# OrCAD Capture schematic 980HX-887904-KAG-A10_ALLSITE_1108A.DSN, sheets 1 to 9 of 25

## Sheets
1 P0043_S4_POWER: size A2
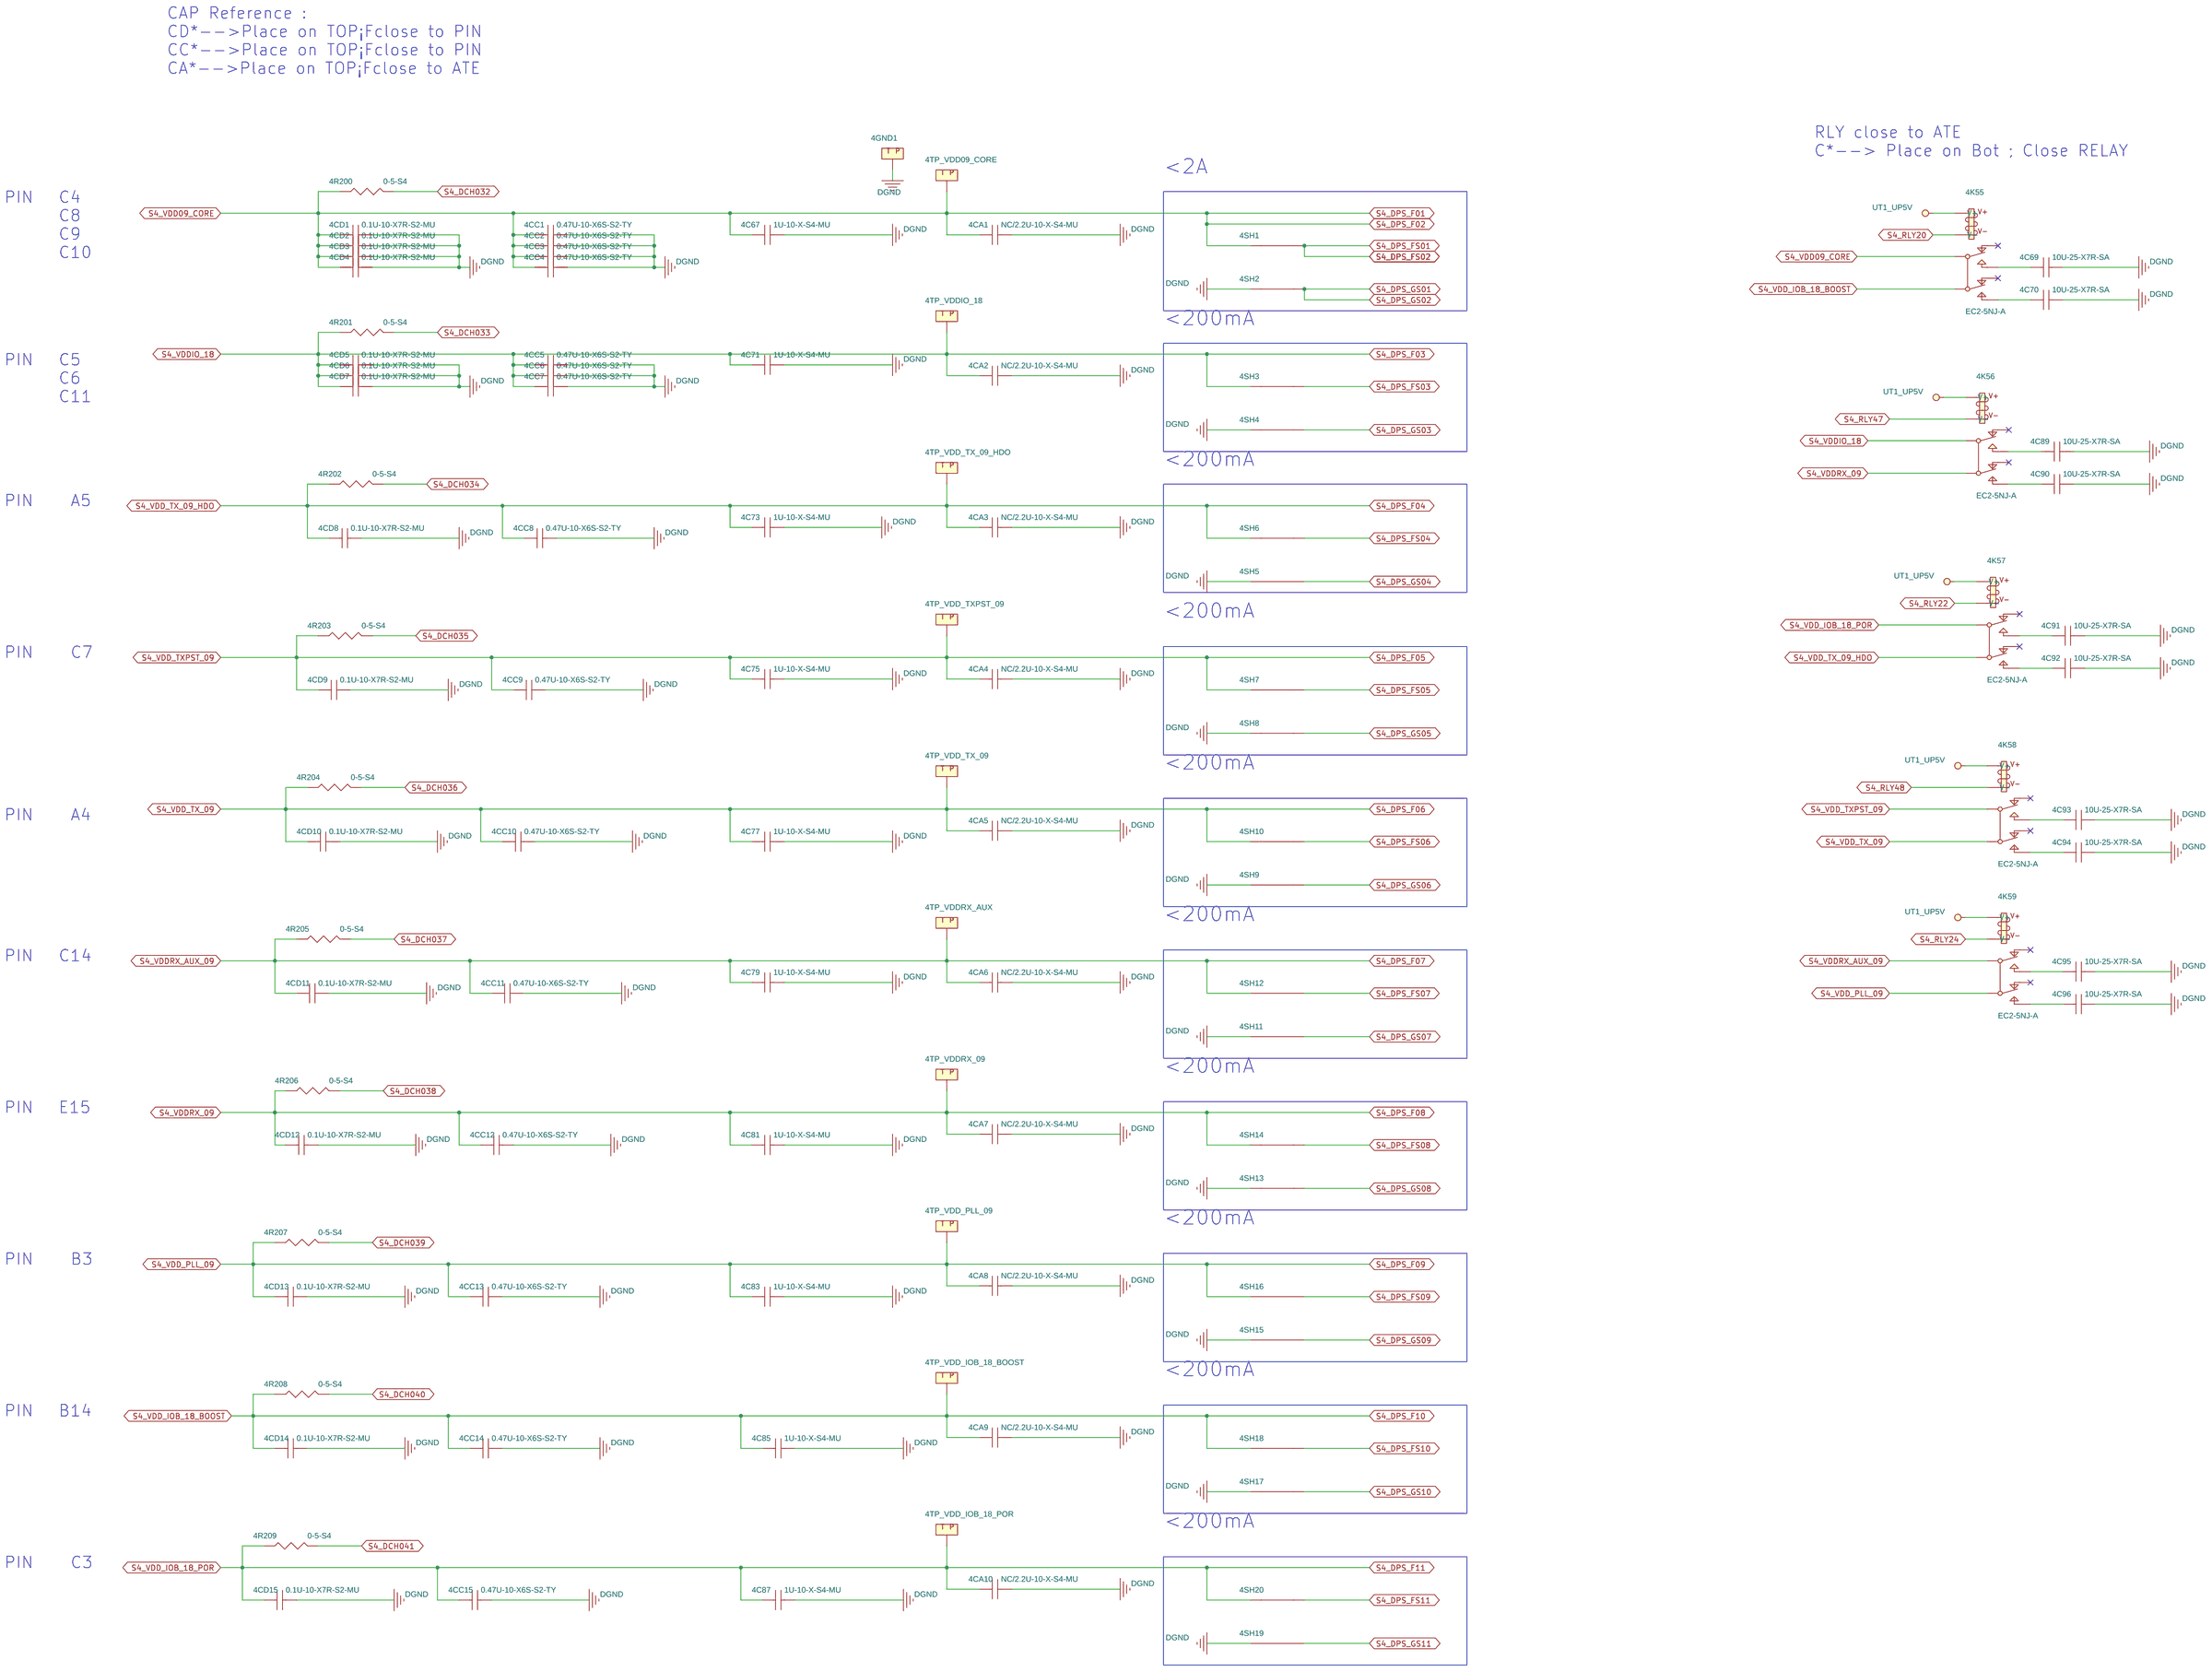
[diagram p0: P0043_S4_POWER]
2 P0042_S4_FLASH_I2C: size A4
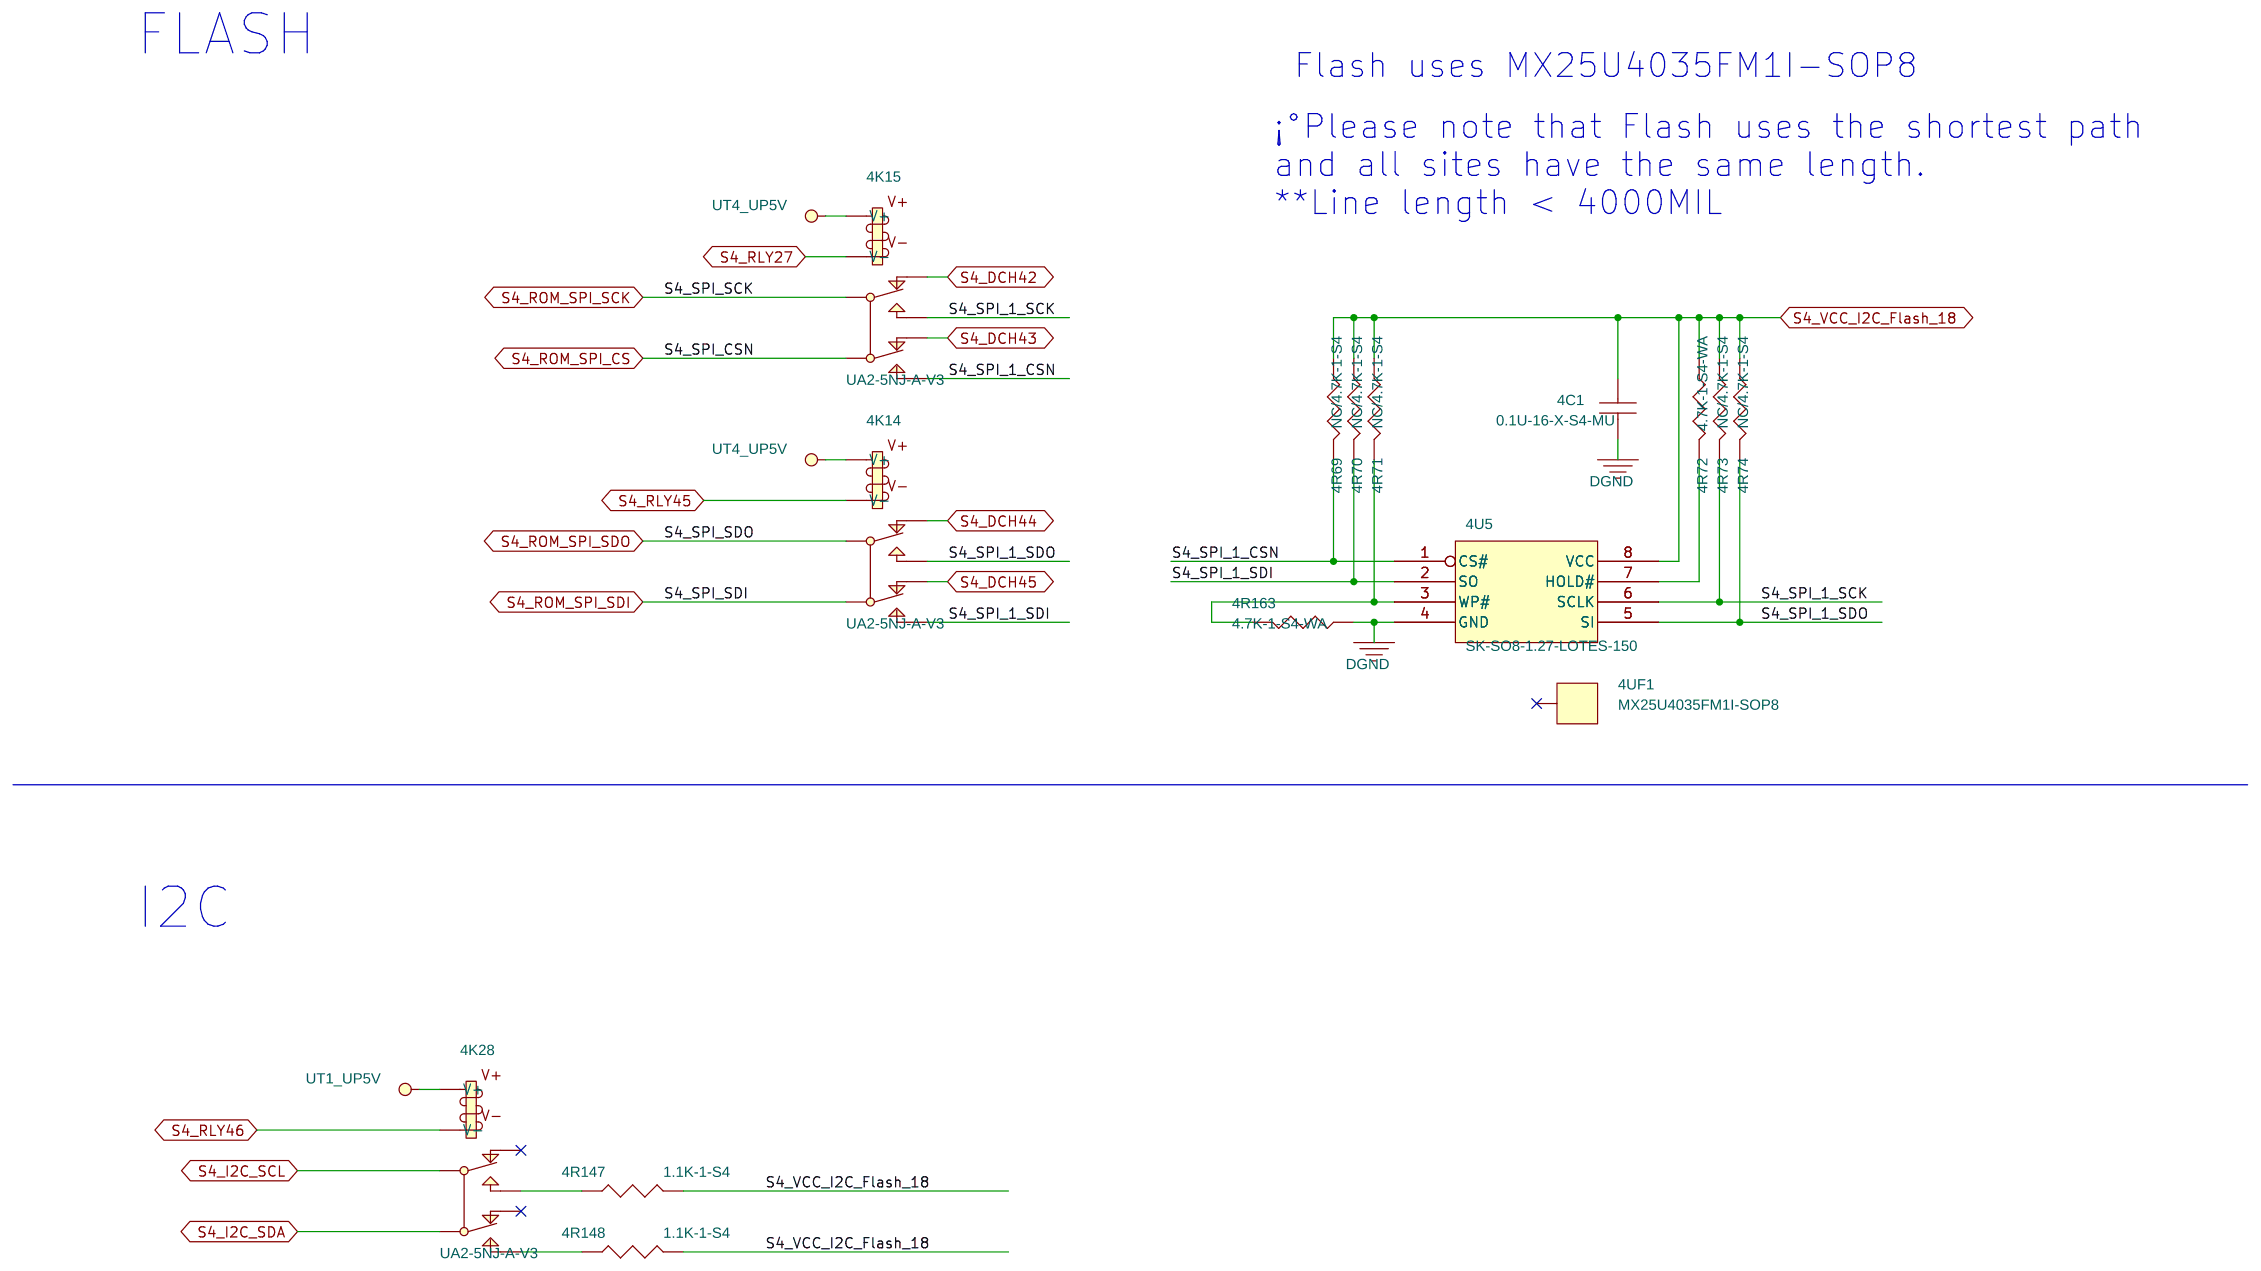
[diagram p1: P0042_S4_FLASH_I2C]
3 P0041_S4_DUT: size A2
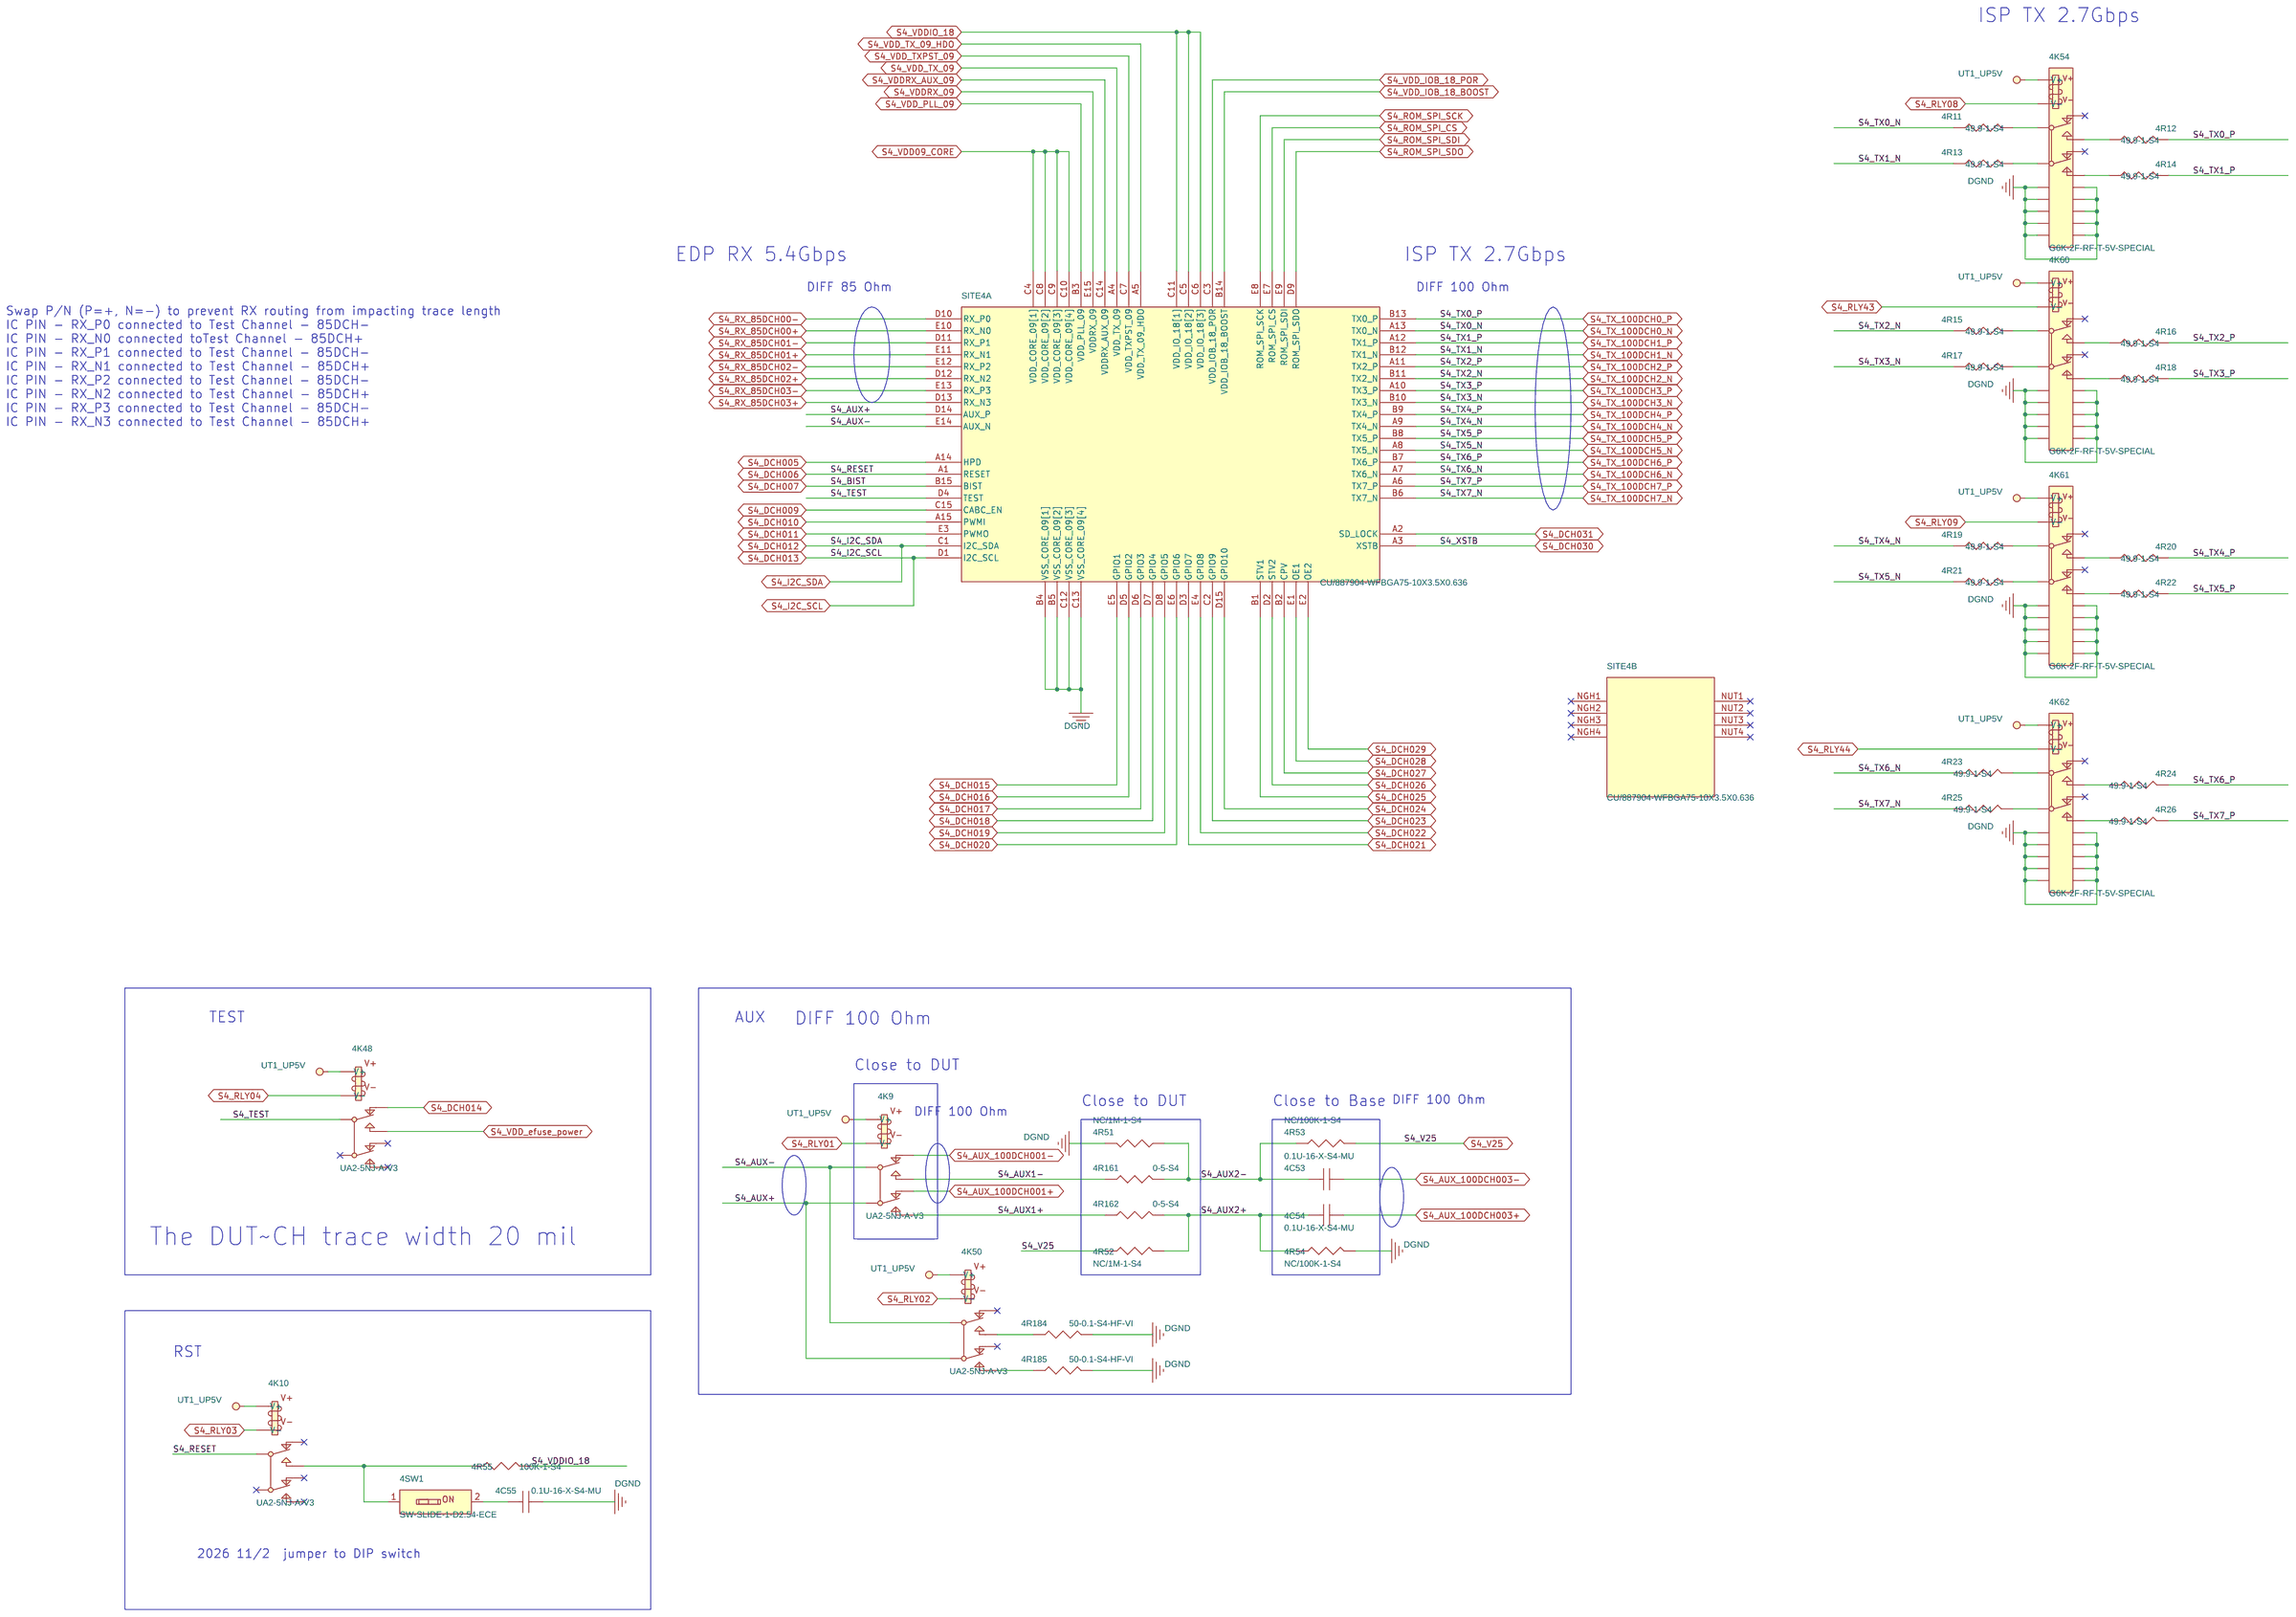
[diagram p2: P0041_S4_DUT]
4 P0033_S3_POWER: size A2
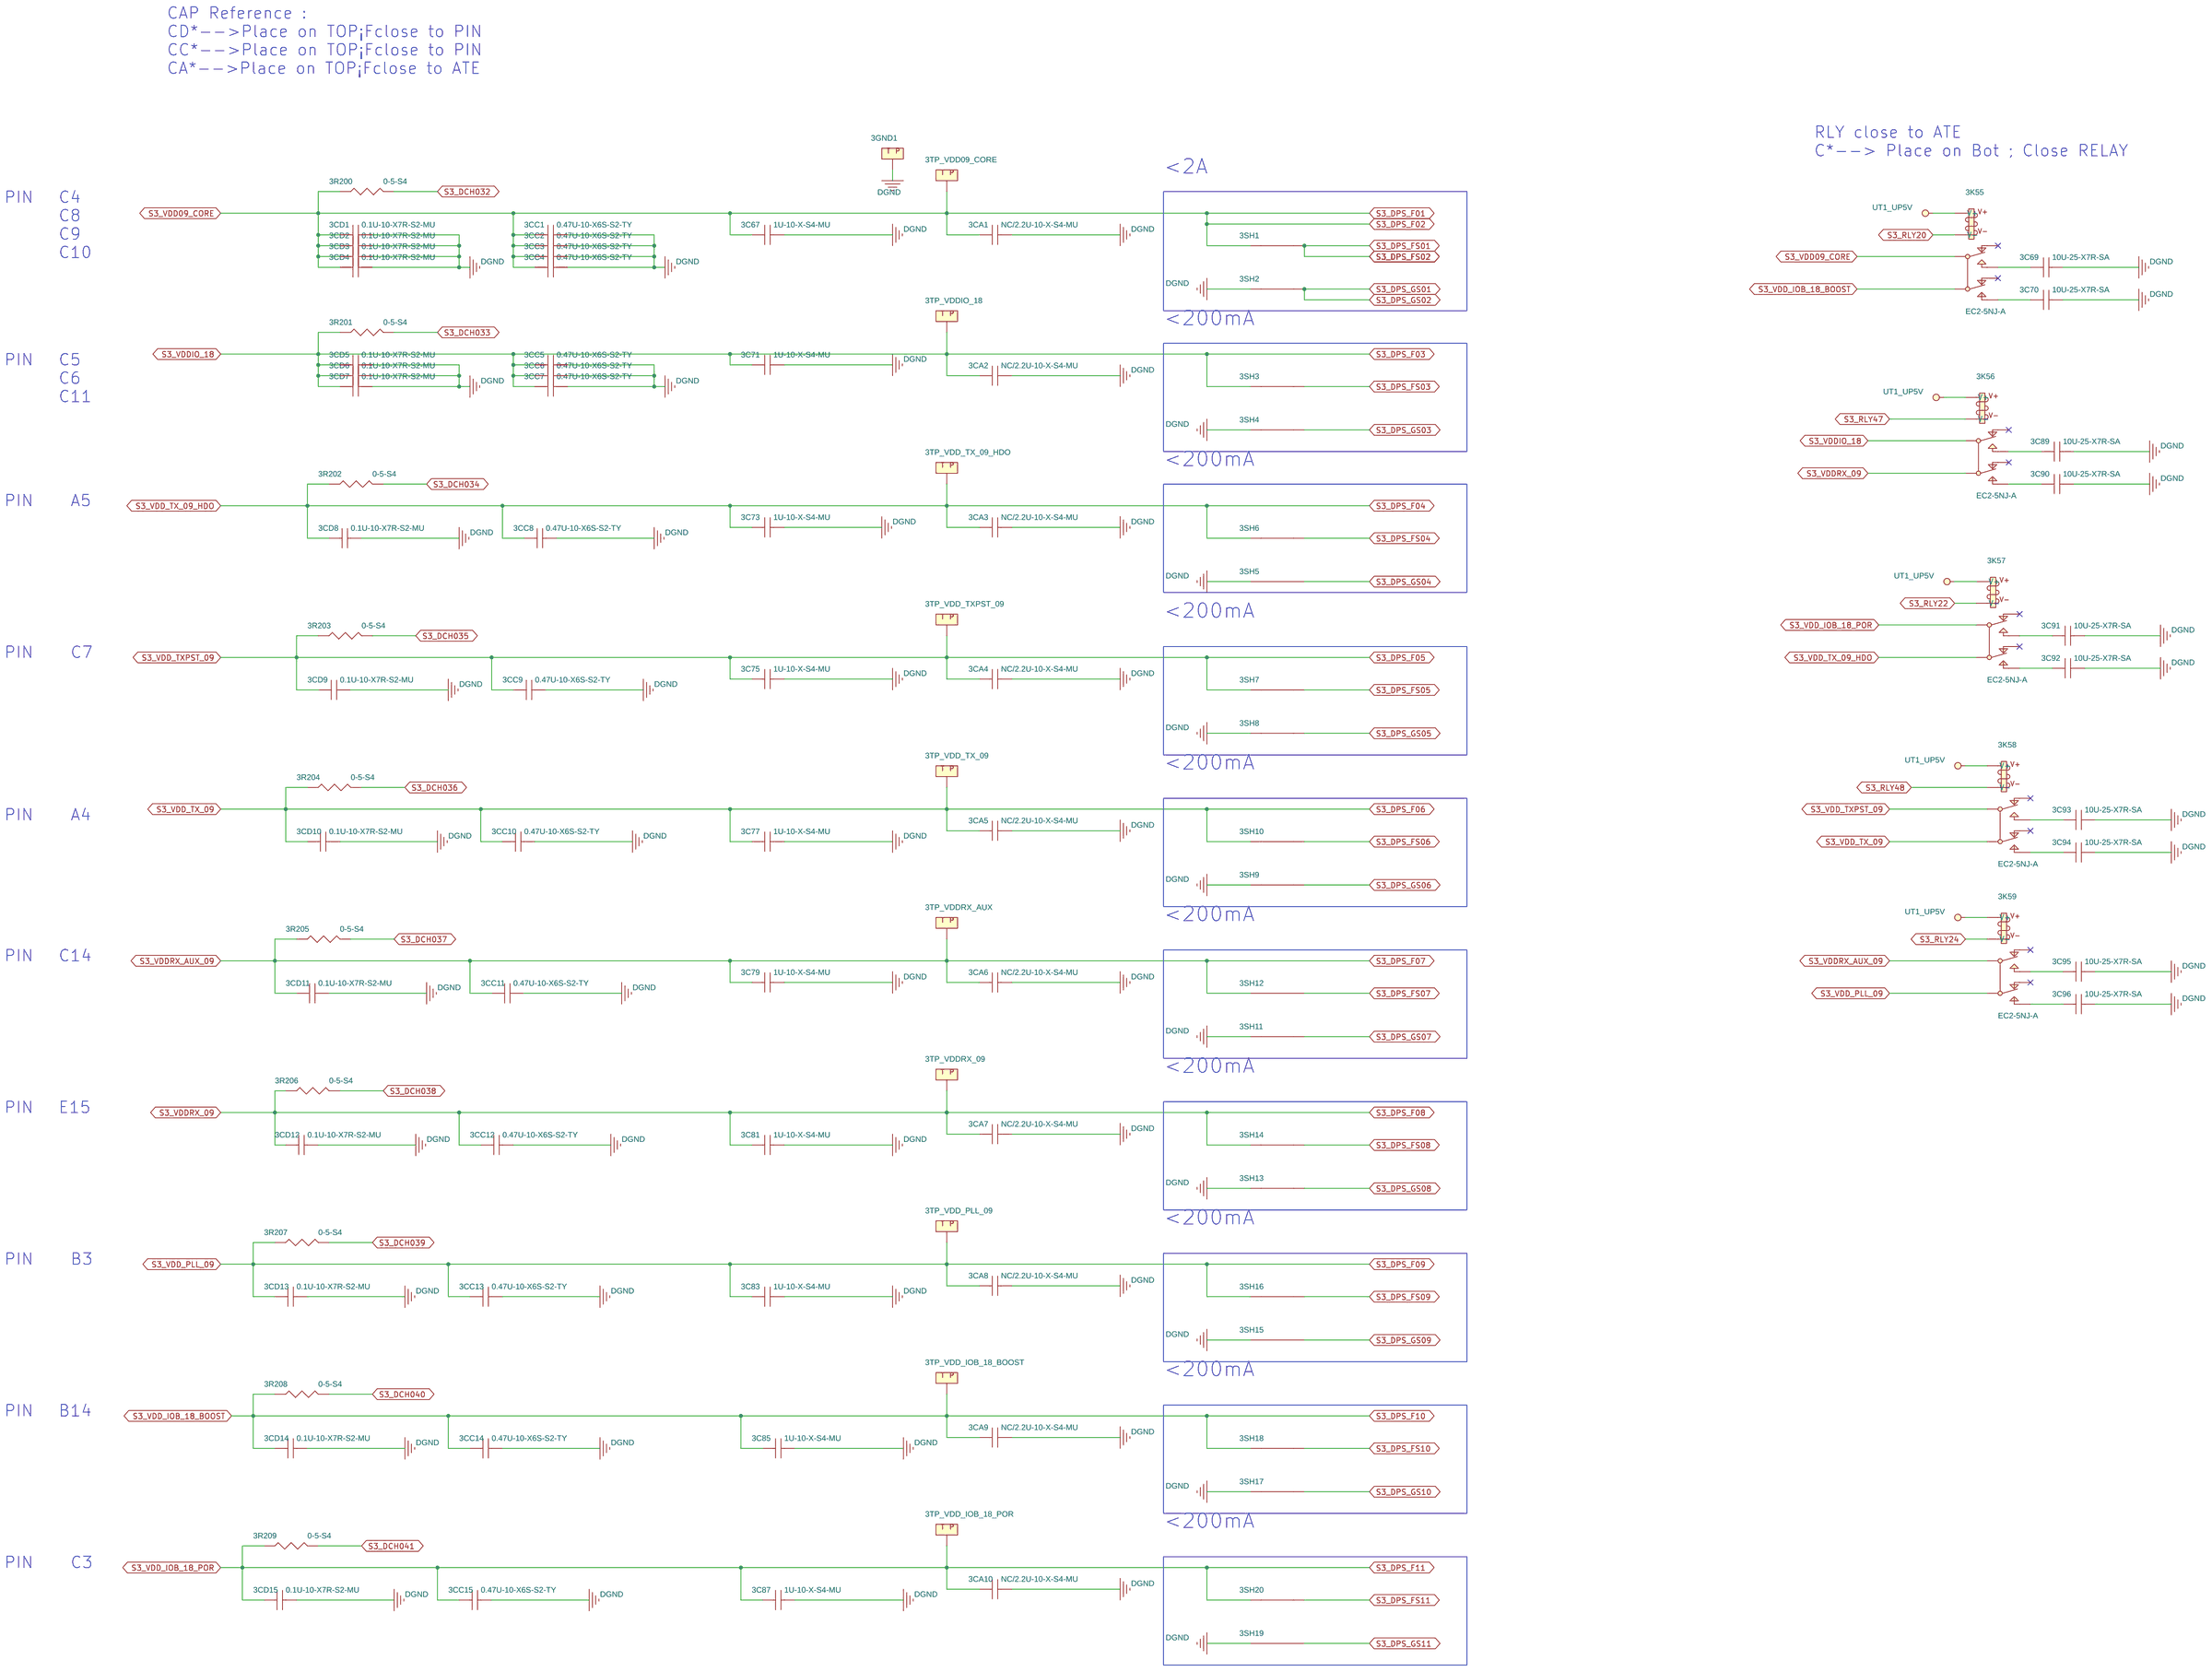
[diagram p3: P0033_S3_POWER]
5 P0032_S3_FLASH_I2C: size A4
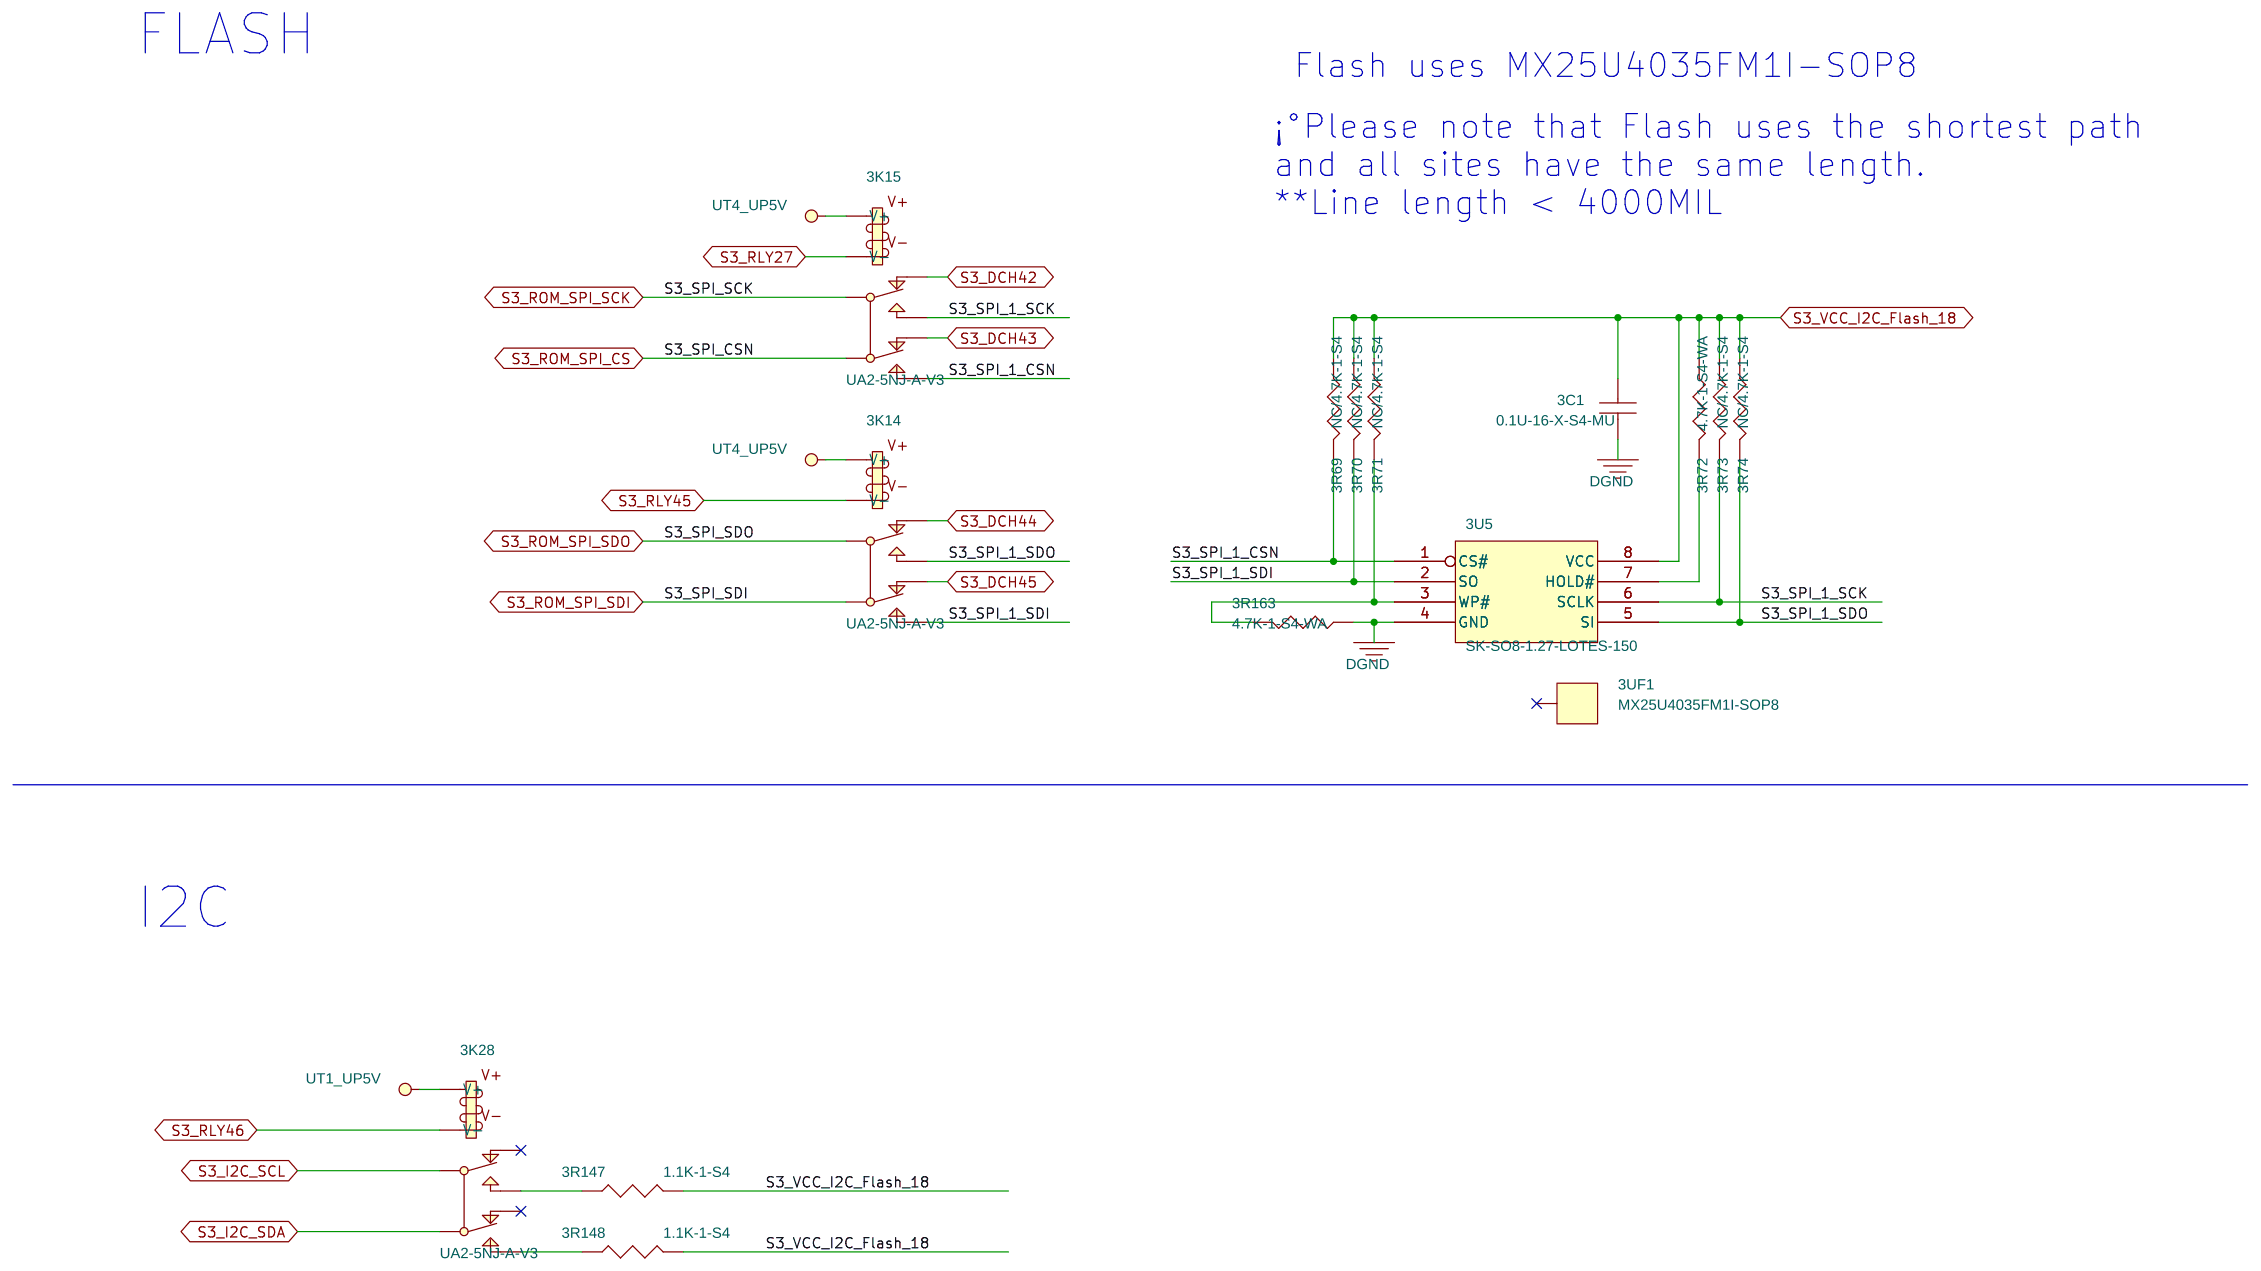
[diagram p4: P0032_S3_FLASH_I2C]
6 P0031_S3_DUT: size A2
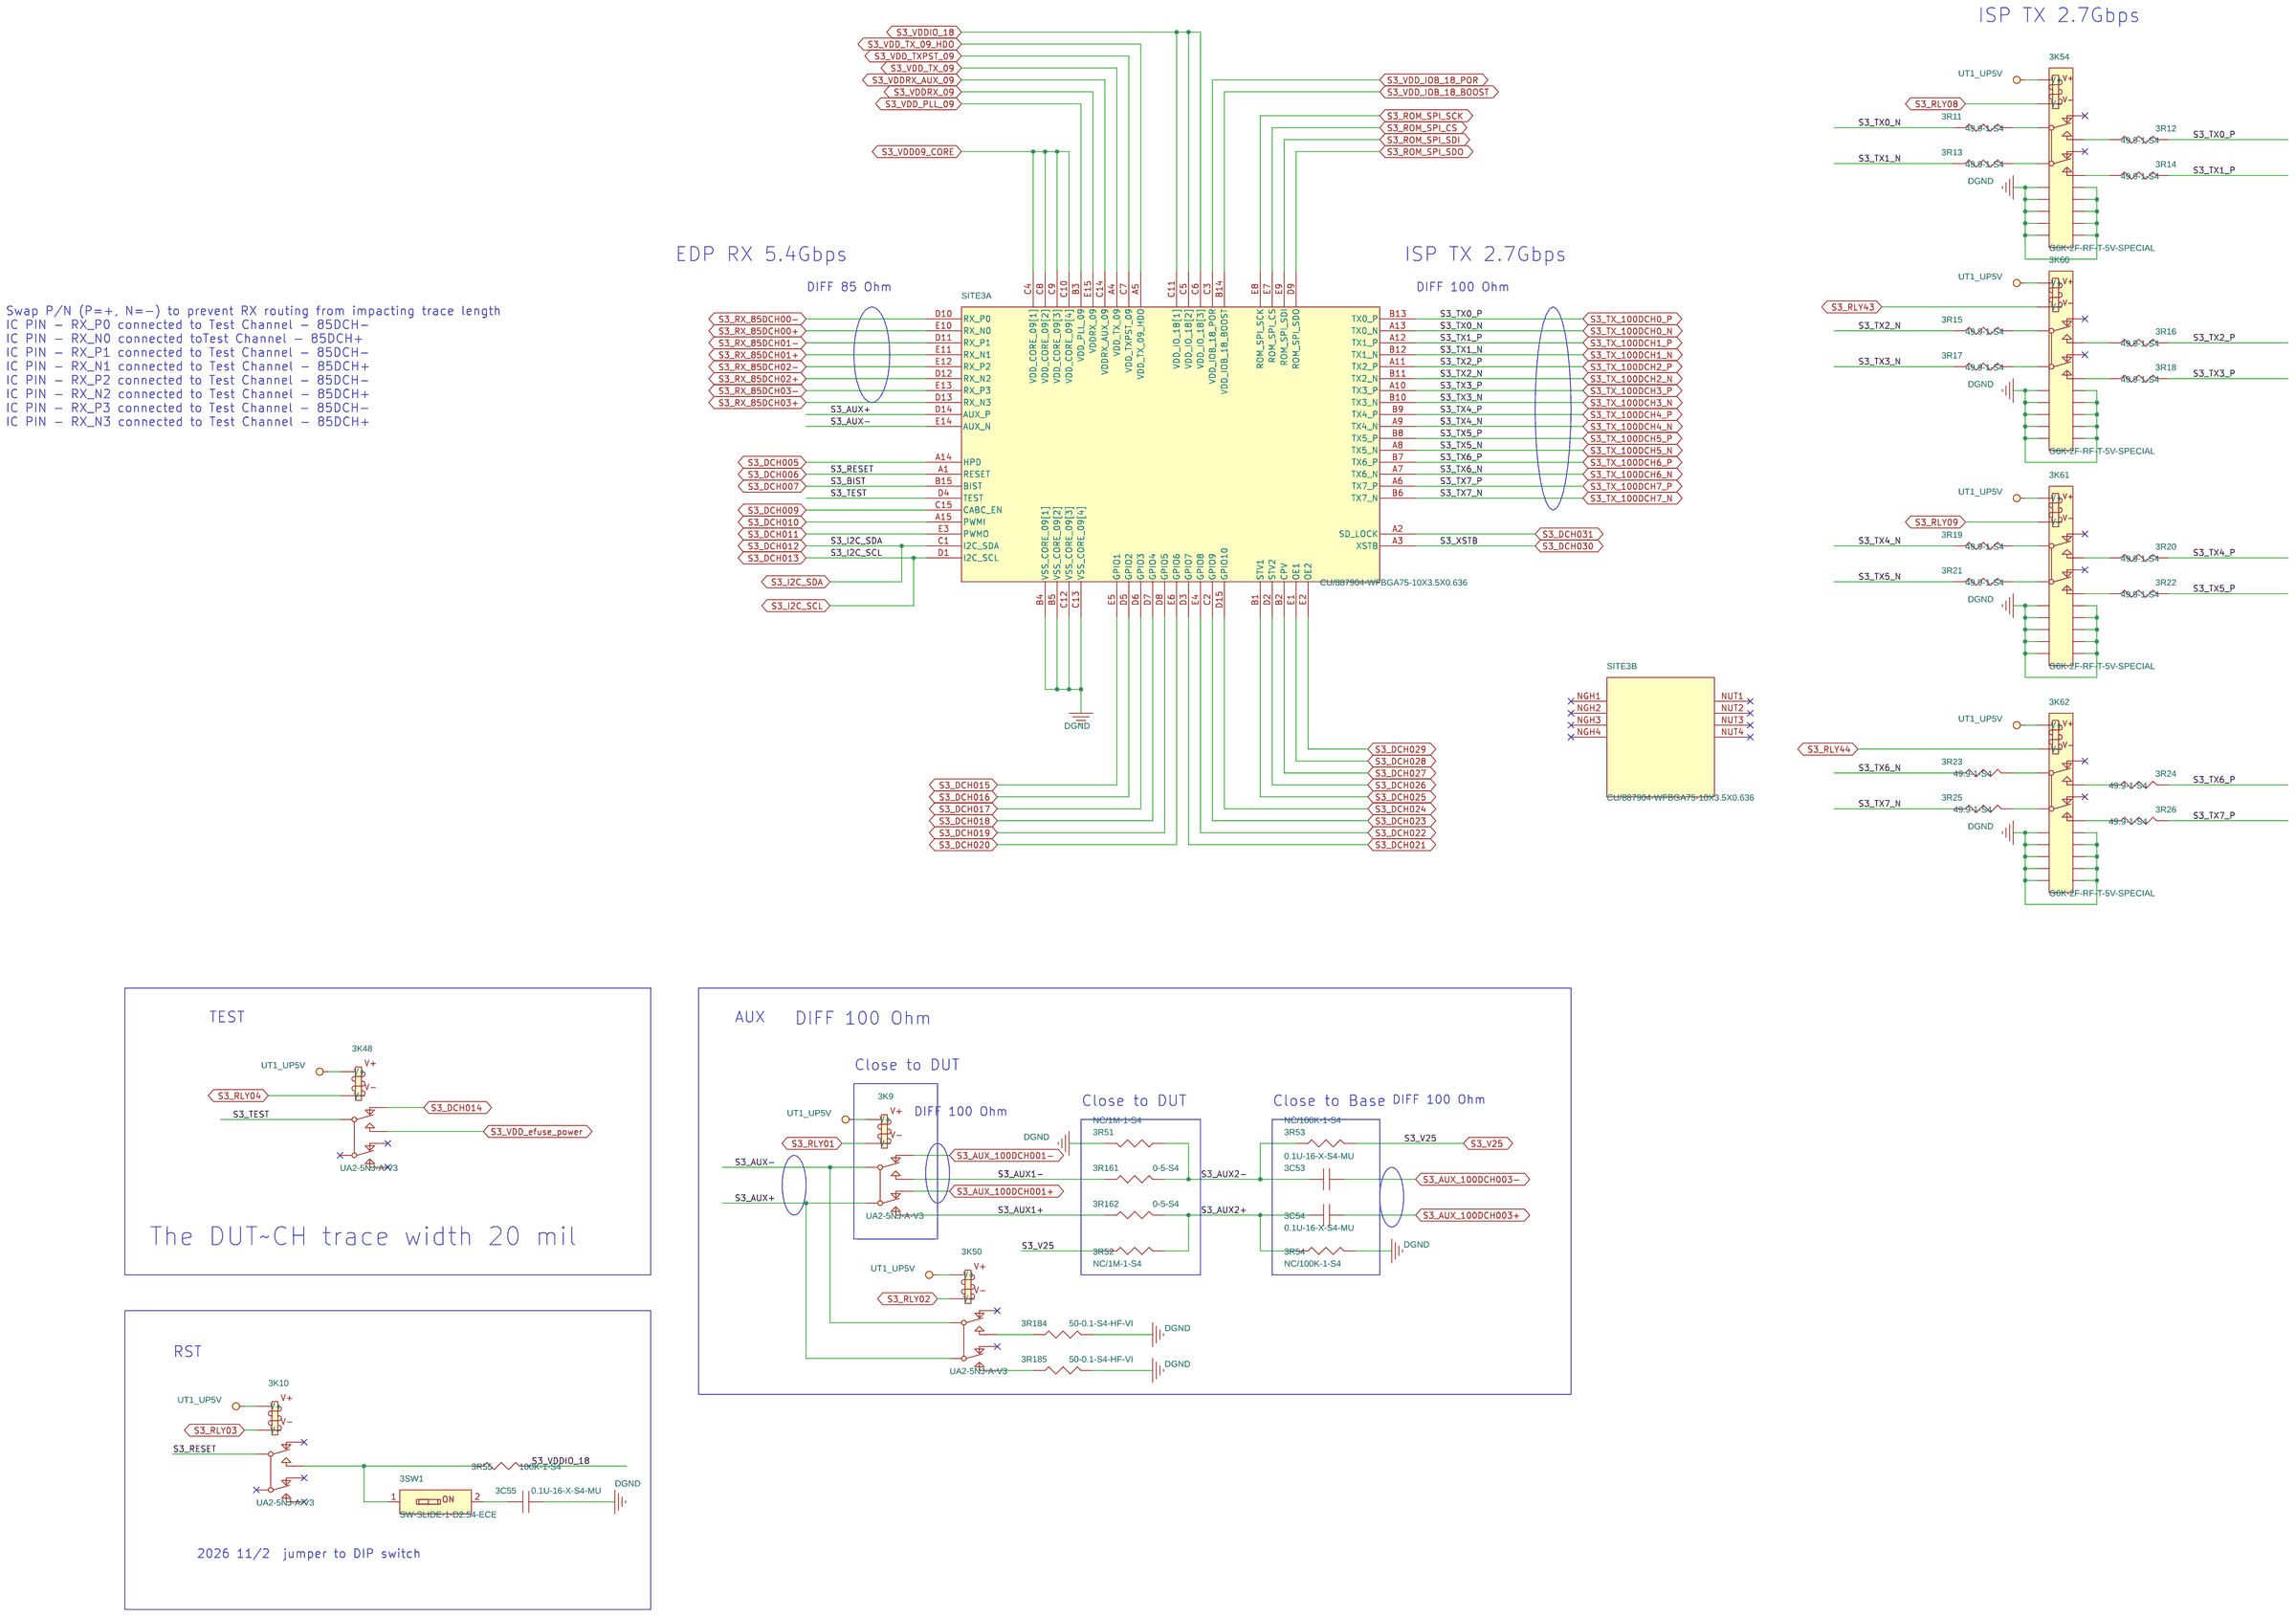
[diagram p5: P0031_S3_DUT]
7 P0023_S2_POWER: size A2
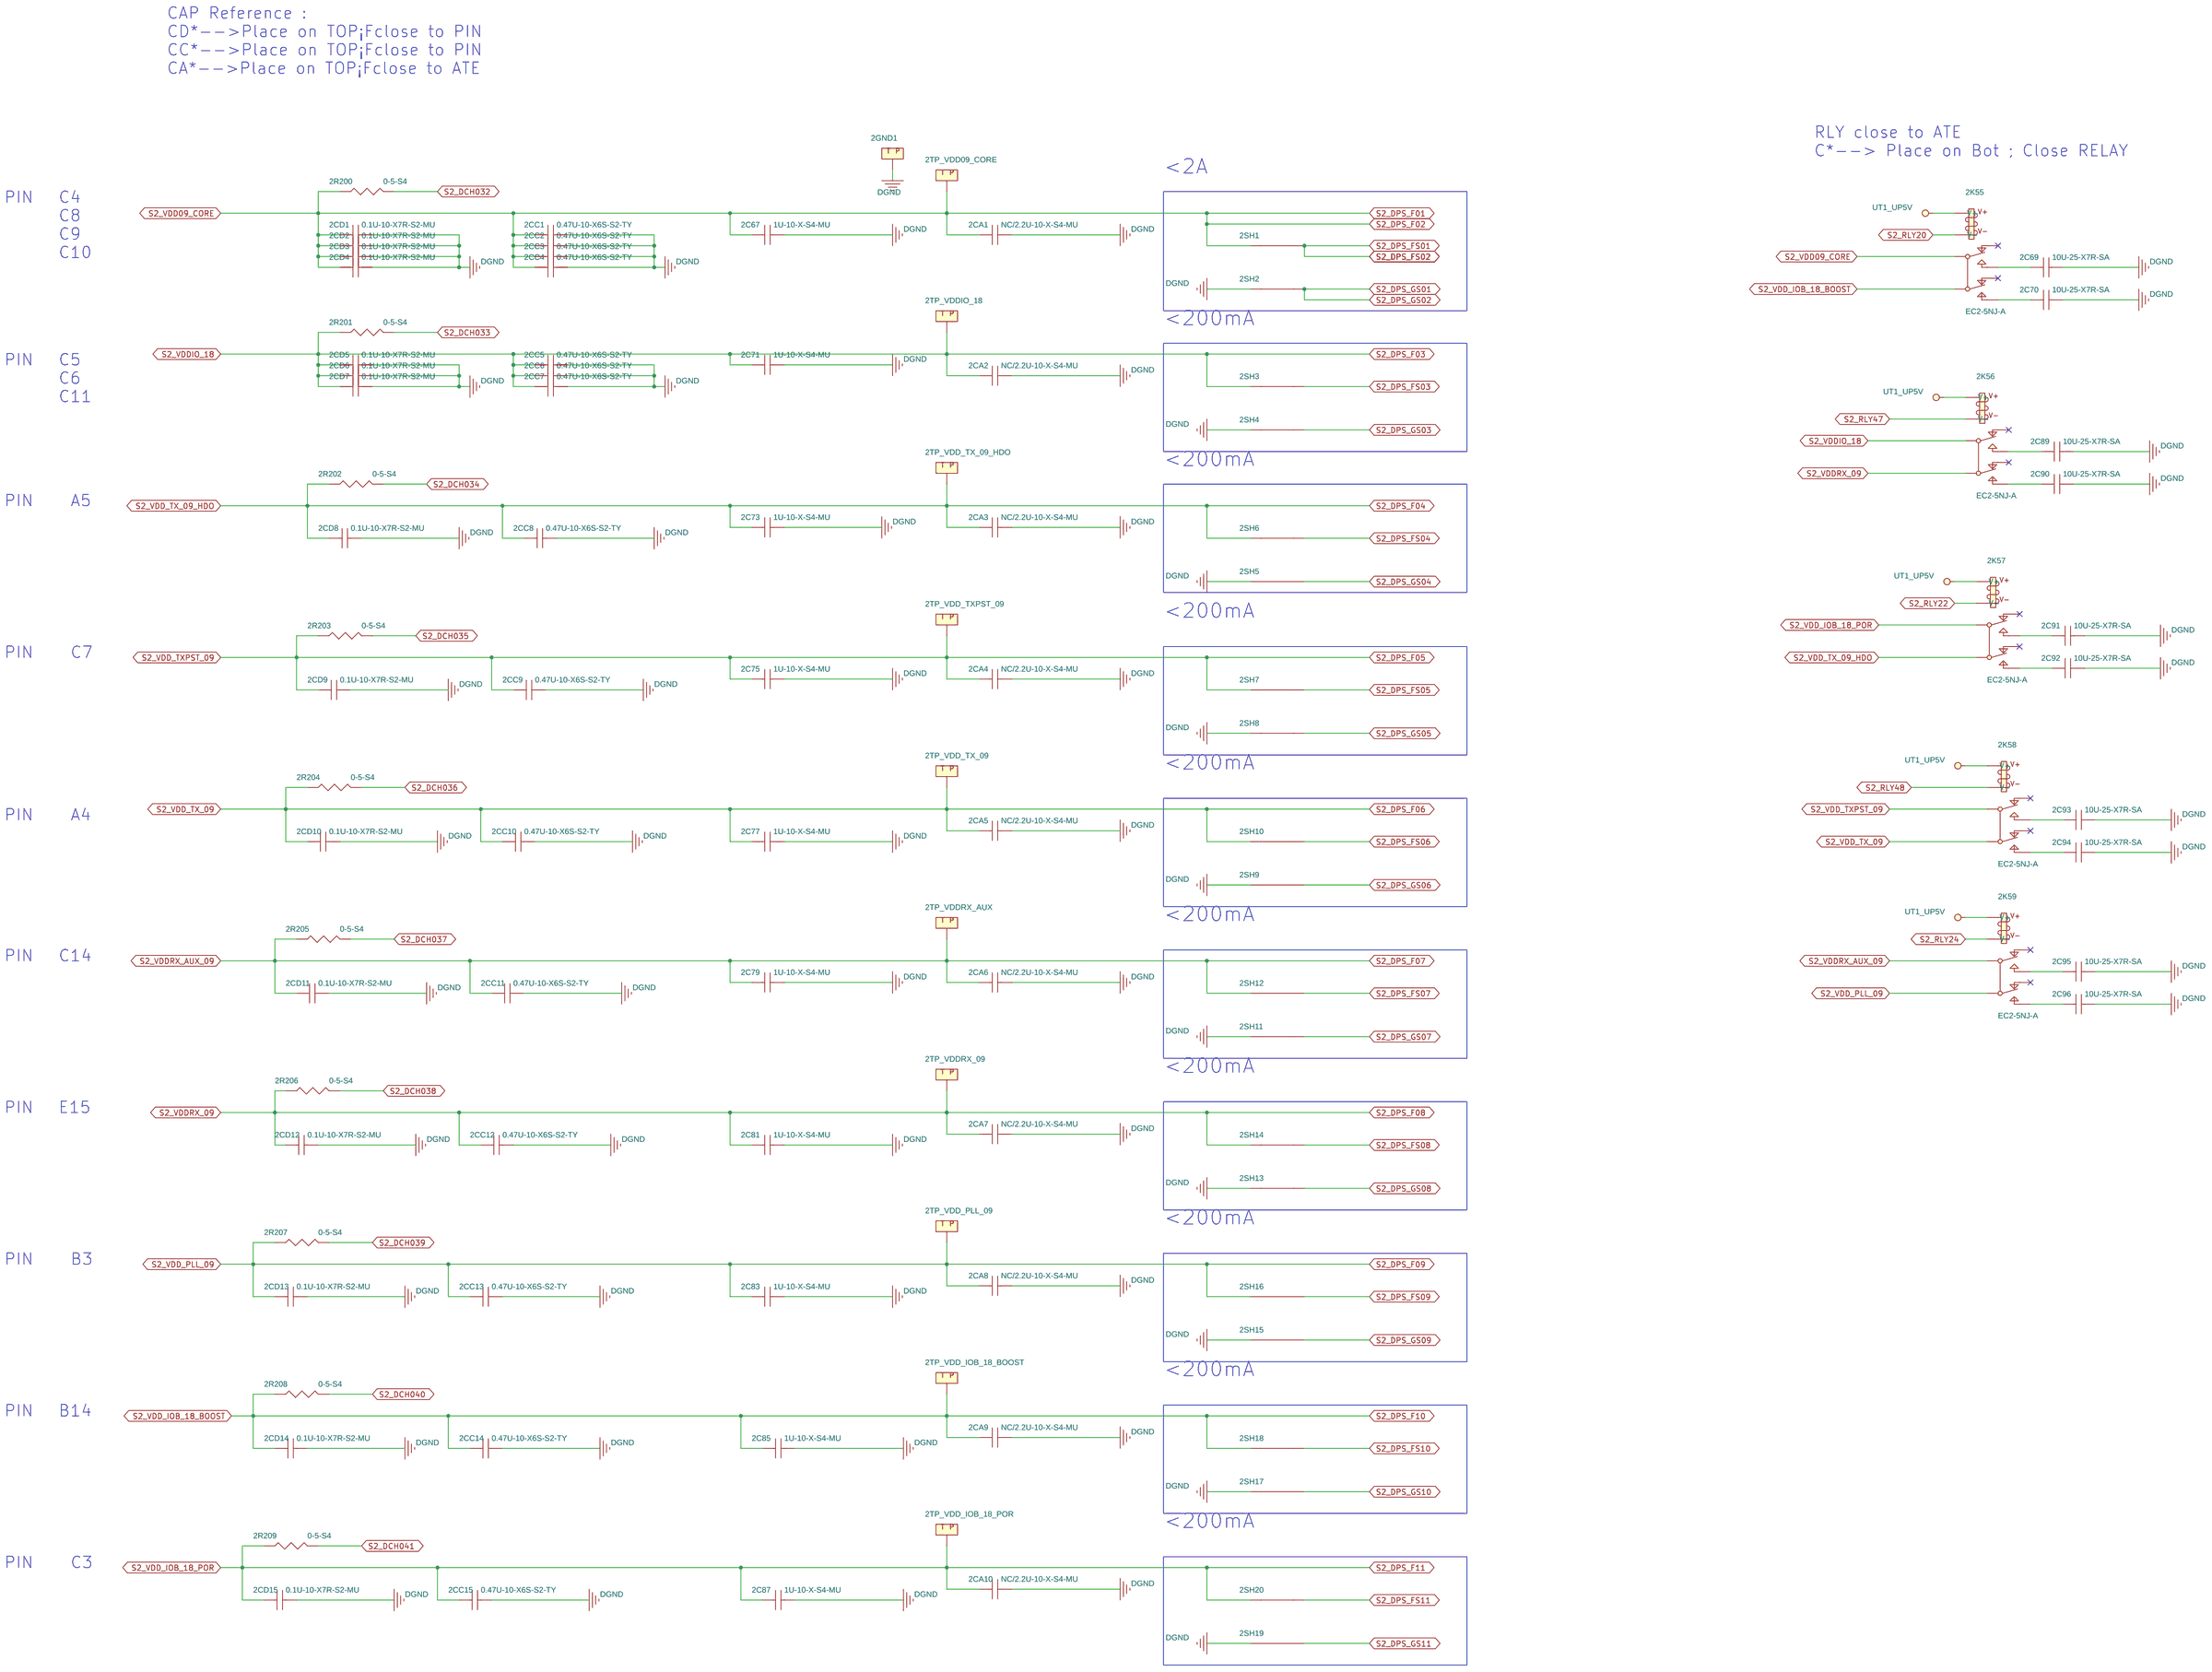
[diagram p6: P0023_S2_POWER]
8 P0022_S2_FLASH_I2C: size A4
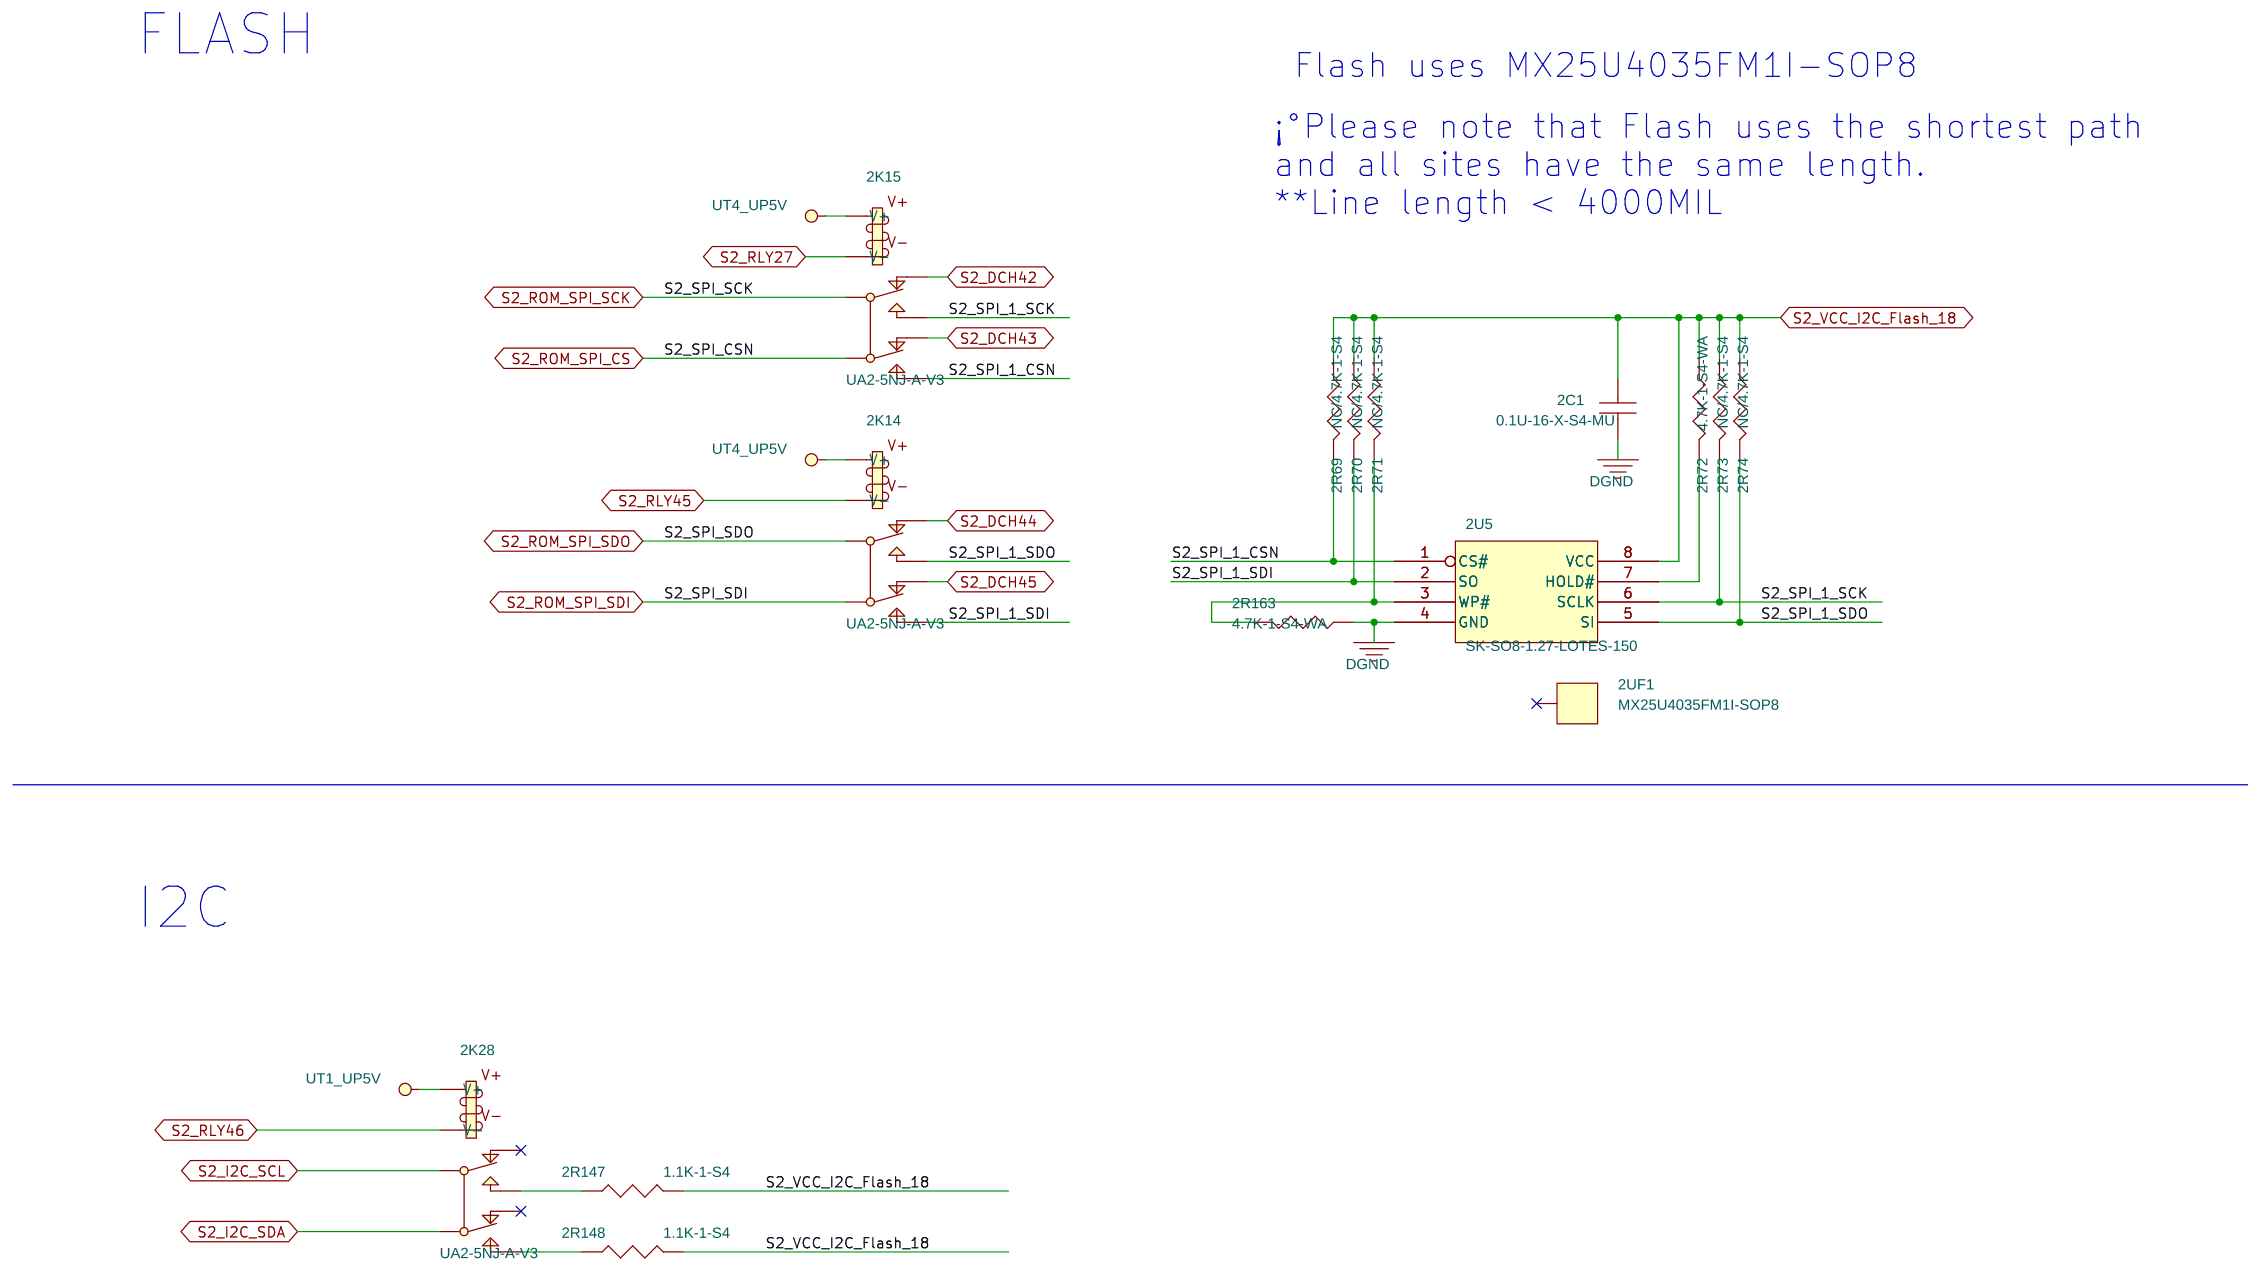
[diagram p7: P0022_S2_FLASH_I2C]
9 P0021_S2_DUT: size A2
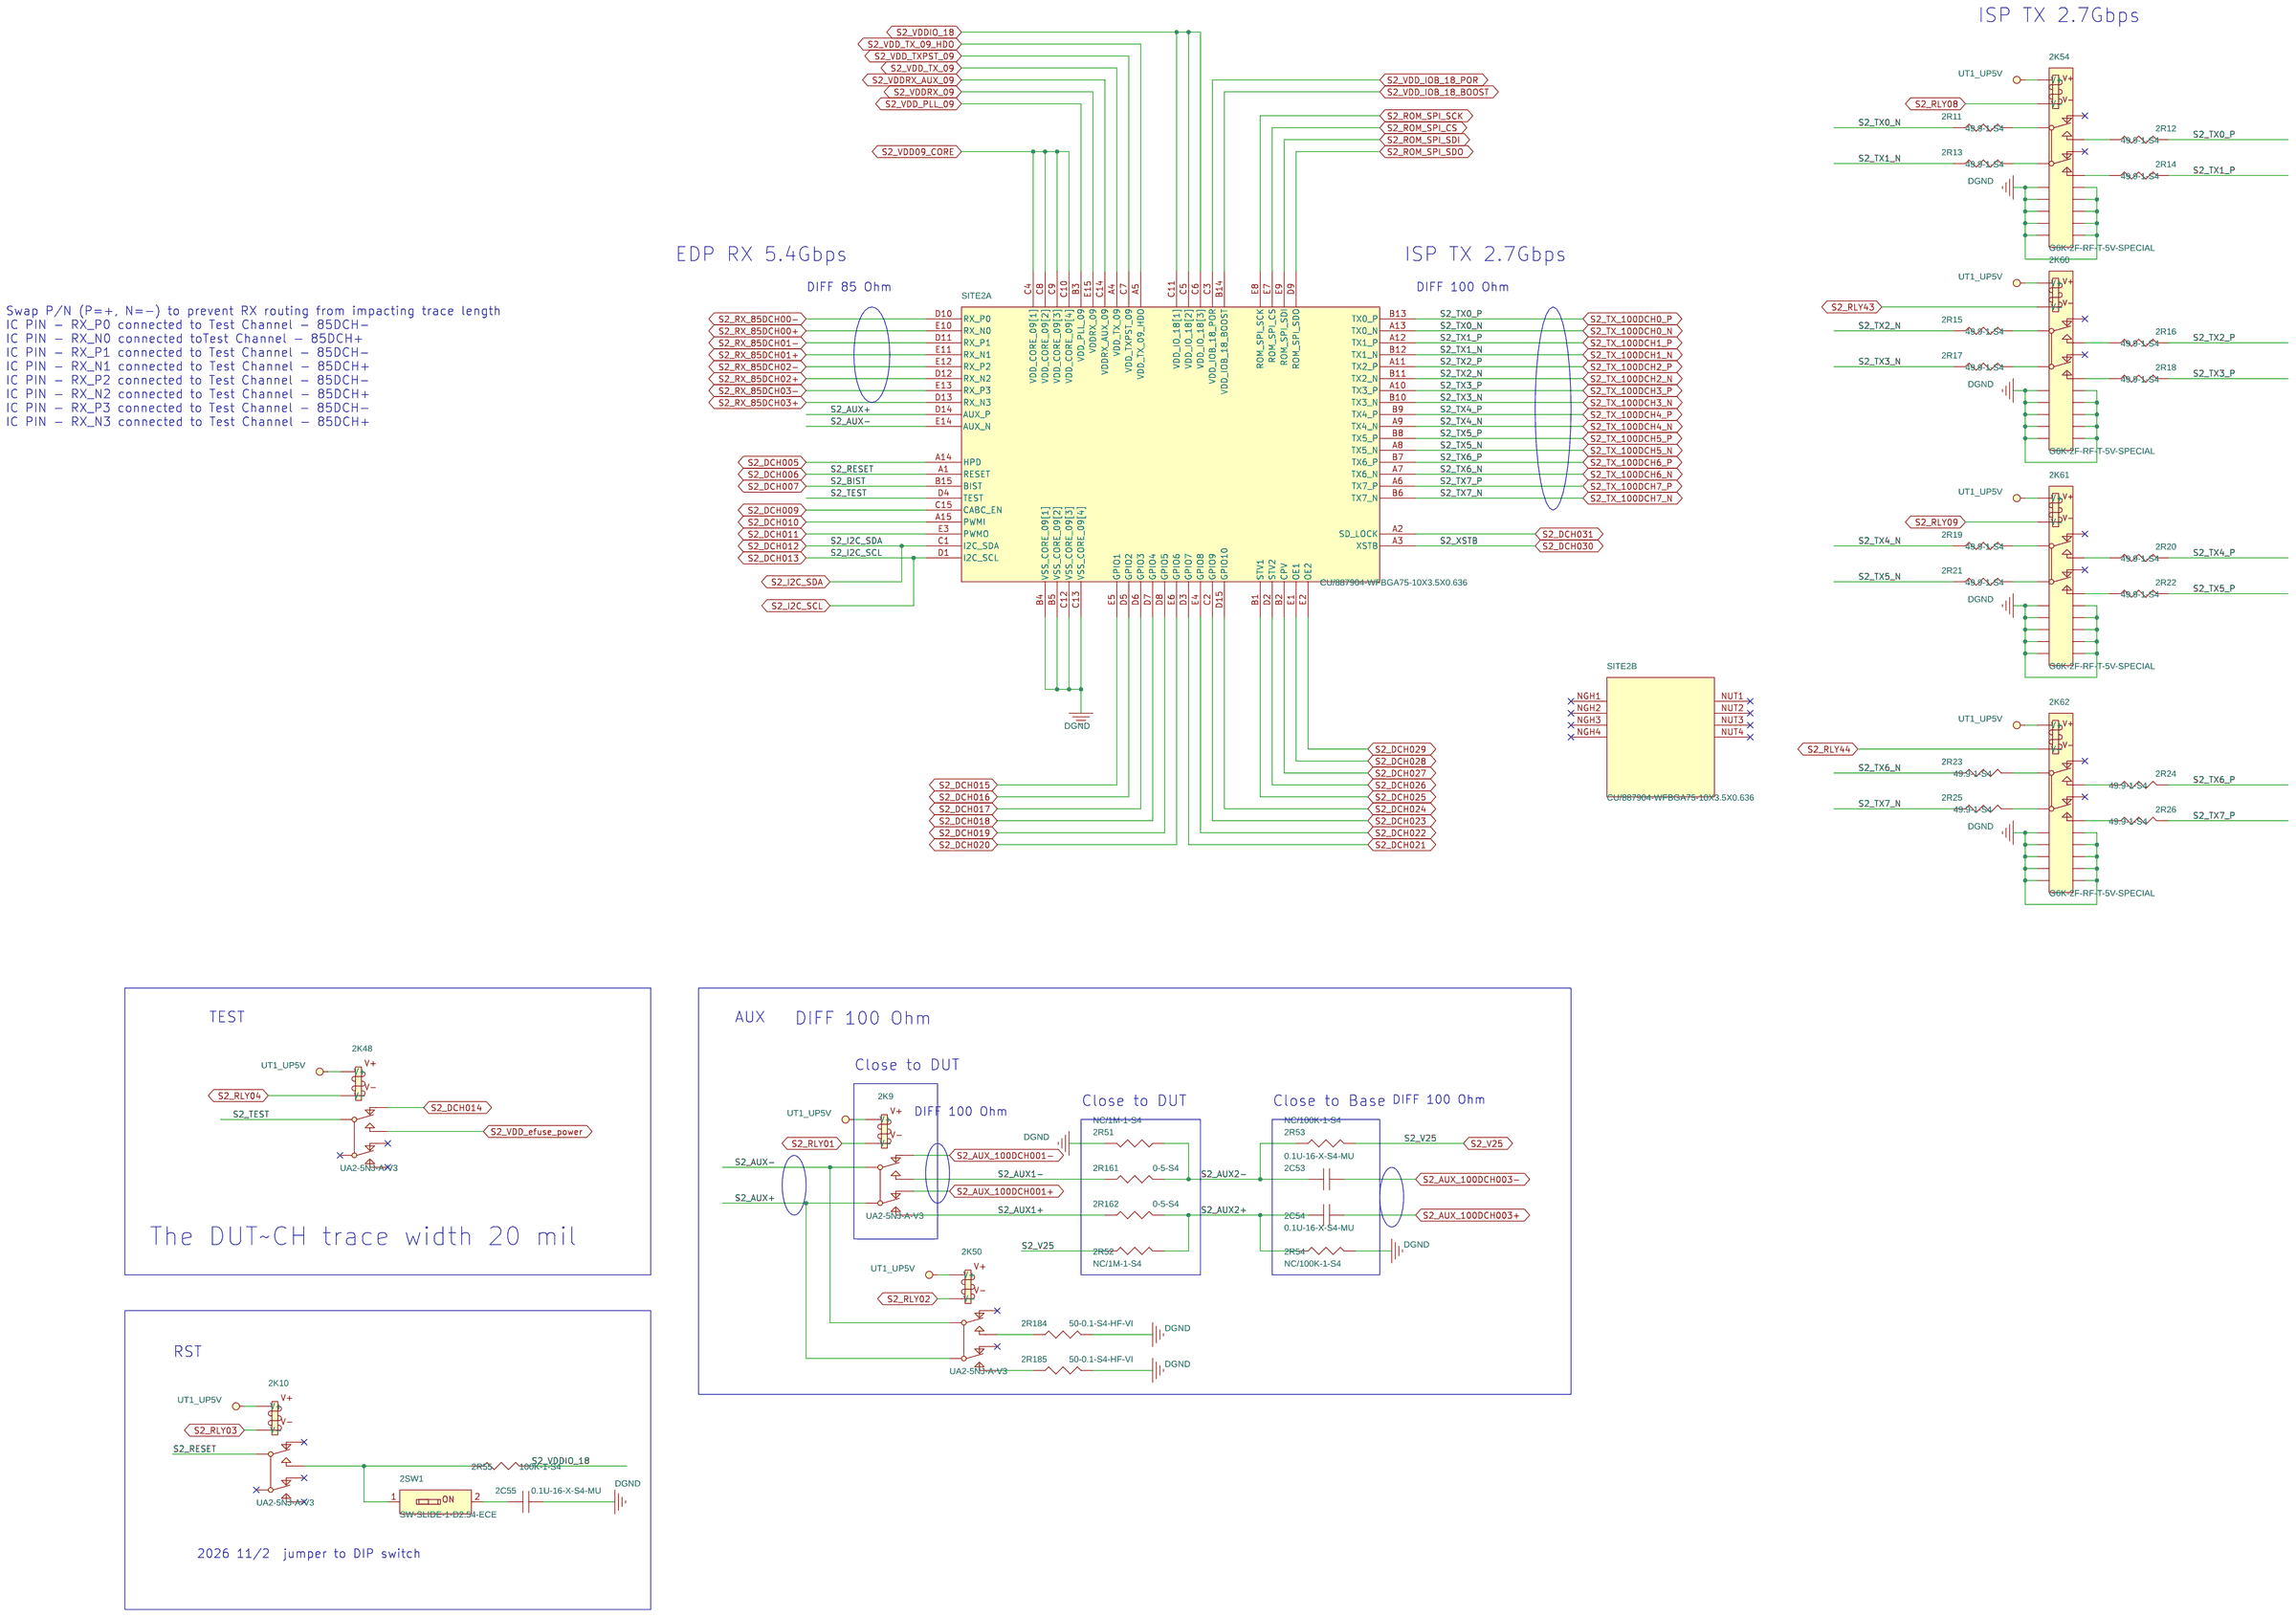
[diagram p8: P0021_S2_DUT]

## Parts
sheet P0021_S2_DUT
2C53  0.1U-16-X-S4-MU  [C0402]
2C54  0.1U-16-X-S4-MU  [C0402]
2C55  0.1U-16-X-S4-MU  [C0402]
2K9  UA2-5NJ-A-V3  [RL_NECUA2_5V_V3]
2K10  UA2-5NJ-A-V3  [RL_NECUA2_5V_V3]
2K48  UA2-5NJ-A-V3  [RL_NECUA2_5V_V3]
2K50  UA2-5NJ-A-V3  [RL_NECUA2_5V_V3]
2K54  G6K-2F-RF-T-5V-SPECIAL  [RL_G6K2FRT_8P_5V_GR]
2K60  G6K-2F-RF-T-5V-SPECIAL  [RL_G6K2FRT_8P_5V_GR]
2K61  G6K-2F-RF-T-5V-SPECIAL  [RL_G6K2FRT_8P_5V_GR]
2K62  G6K-2F-RF-T-5V-SPECIAL  [RL_G6K2FRT_8P_5V_GR]
2R11  49.9-1-S4  [R0402]
2R12  49.9-1-S4  [R0402]
2R13  49.9-1-S4  [R0402]
2R14  49.9-1-S4  [R0402]
2R15  49.9-1-S4  [R0402]
2R16  49.9-1-S4  [R0402]
2R17  49.9-1-S4  [R0402]
2R18  49.9-1-S4  [R0402]
2R19  49.9-1-S4  [R0402]
2R20  49.9-1-S4  [R0402]
2R21  49.9-1-S4  [R0402]
2R22  49.9-1-S4  [R0402]
2R23  49.9-1-S4  [R0402]
2R24  49.9-1-S4  [R0402]
2R25  49.9-1-S4  [R0402]
2R26  49.9-1-S4  [R0402]
2R51  NC/1M-1-S4  [R0402]
2R52  NC/1M-1-S4  [R0402]
2R53  NC/100K-1-S4  [R0402]
2R54  NC/100K-1-S4  [R0402]
2R55  100K-1-S4  [R0402]
2R161  0-5-S4  [R0402]
2R162  0-5-S4  [R0402]
2R184  50-0.1-S4-HF-VI  [R0402]
2R185  50-0.1-S4-HF-VI  [R0402]
2SW1  SW-SLIDE-1-D2.54-ECE  [SW_DIPX1_2P_H5MM]
SITE2  CU/887904-WFBGA75-10X3.5X0.636  [SK_WFBGA75P_0P65MM_JG_887904]  (sections A,B)
sheet P0022_S2_FLASH_I2C
2C1  0.1U-16-X-S4-MU  [C0402]
2K14  UA2-5NJ-A-V3  [RL_NECUA2_5V_V3]
2K15  UA2-5NJ-A-V3  [RL_NECUA2_5V_V3]
2K28  UA2-5NJ-A-V3  [RL_NECUA2_5V_V3]
2R69  NC/4.7K-1-S4  [R0402]
2R70  NC/4.7K-1-S4  [R0402]
2R71  NC/4.7K-1-S4  [R0402]
2R72  4.7K-1-S4-WA  [R0402]
2R73  NC/4.7K-1-S4  [R0402]
2R74  NC/4.7K-1-S4  [R0402]
2R147  1.1K-1-S4  [R0402]
2R148  1.1K-1-S4  [R0402]
2R163  4.7K-1-S4-WA  [R0402]
2U5  SK-SO8-1.27-LOTES-150  [SK_SO8_150_1P27MM_LOTES]
2UF1  MX25U4035FM1I-SOP8  [SOCKET_CODE]
sheet P0023_S2_POWER
2C67  1U-10-X-S4-MU  [C0402]
2C69  10U-25-X7R-SA  [C1206]
2C70  10U-25-X7R-SA  [C1206]
2C71  1U-10-X-S4-MU  [C0402]
2C73  1U-10-X-S4-MU  [C0402]
2C75  1U-10-X-S4-MU  [C0402]
2C77  1U-10-X-S4-MU  [C0402]
2C79  1U-10-X-S4-MU  [C0402]
2C81  1U-10-X-S4-MU  [C0402]
2C83  1U-10-X-S4-MU  [C0402]
2C85  1U-10-X-S4-MU  [C0402]
2C87  1U-10-X-S4-MU  [C0402]
2C89  10U-25-X7R-SA  [C1206]
2C90  10U-25-X7R-SA  [C1206]
2C91  10U-25-X7R-SA  [C1206]
2C92  10U-25-X7R-SA  [C1206]
2C93  10U-25-X7R-SA  [C1206]
2C94  10U-25-X7R-SA  [C1206]
2C95  10U-25-X7R-SA  [C1206]
2C96  10U-25-X7R-SA  [C1206]
2CA1  NC/2.2U-10-X-S4-MU  [C0402]
2CA2  NC/2.2U-10-X-S4-MU  [C0402]
2CA3  NC/2.2U-10-X-S4-MU  [C0402]
2CA4  NC/2.2U-10-X-S4-MU  [C0402]
2CA5  NC/2.2U-10-X-S4-MU  [C0402]
2CA6  NC/2.2U-10-X-S4-MU  [C0402]
2CA7  NC/2.2U-10-X-S4-MU  [C0402]
2CA8  NC/2.2U-10-X-S4-MU  [C0402]
2CA9  NC/2.2U-10-X-S4-MU  [C0402]
2CA10  NC/2.2U-10-X-S4-MU  [C0402]
2CC1  0.47U-10-X6S-S2-TY  [C0201]
2CC2  0.47U-10-X6S-S2-TY  [C0201]
2CC3  0.47U-10-X6S-S2-TY  [C0201]
2CC4  0.47U-10-X6S-S2-TY  [C0201]
2CC5  0.47U-10-X6S-S2-TY  [C0201]
2CC6  0.47U-10-X6S-S2-TY  [C0201]
2CC7  0.47U-10-X6S-S2-TY  [C0201]
2CC8  0.47U-10-X6S-S2-TY  [C0201]
2CC9  0.47U-10-X6S-S2-TY  [C0201]
2CC10  0.47U-10-X6S-S2-TY  [C0201]
2CC11  0.47U-10-X6S-S2-TY  [C0201]
2CC12  0.47U-10-X6S-S2-TY  [C0201]
2CC13  0.47U-10-X6S-S2-TY  [C0201]
2CC14  0.47U-10-X6S-S2-TY  [C0201]
2CC15  0.47U-10-X6S-S2-TY  [C0201]
2CD1  0.1U-10-X7R-S2-MU  [C0201]
2CD2  0.1U-10-X7R-S2-MU  [C0201]
2CD3  0.1U-10-X7R-S2-MU  [C0201]
2CD4  0.1U-10-X7R-S2-MU  [C0201]
2CD5  0.1U-10-X7R-S2-MU  [C0201]
2CD6  0.1U-10-X7R-S2-MU  [C0201]
2CD7  0.1U-10-X7R-S2-MU  [C0201]
2CD8  0.1U-10-X7R-S2-MU  [C0201]
2CD9  0.1U-10-X7R-S2-MU  [C0201]
2CD10  0.1U-10-X7R-S2-MU  [C0201]
2CD11  0.1U-10-X7R-S2-MU  [C0201]
2CD12  0.1U-10-X7R-S2-MU  [C0201]
2CD13  0.1U-10-X7R-S2-MU  [C0201]
2CD14  0.1U-10-X7R-S2-MU  [C0201]
2CD15  0.1U-10-X7R-S2-MU  [C0201]
2GND1  TP01  [TP_040_T]
2K55  EC2-5NJ-A  [RL_NECEC2_10P_5V]
2K56  EC2-5NJ-A  [RL_NECEC2_10P_5V]
2K57  EC2-5NJ-A  [RL_NECEC2_10P_5V]
2K58  EC2-5NJ-A  [RL_NECEC2_10P_5V]
2K59  EC2-5NJ-A  [RL_NECEC2_10P_5V]
2R200  0-5-S4  [R0402]
2R201  0-5-S4  [R0402]
2R202  0-5-S4  [R0402]
2R203  0-5-S4  [R0402]
2R204  0-5-S4  [R0402]
2R205  0-5-S4  [R0402]
2R206  0-5-S4  [R0402]
2R207  0-5-S4  [R0402]
2R208  0-5-S4  [R0402]
2R209  0-5-S4  [R0402]
2SH1  SHORT  [DEFAULT_SHORT_SMALL]
2SH2  SHORT  [DEFAULT_SHORT_SMALL]
2SH3  SHORT  [DEFAULT_SHORT_SMALL]
2SH4  SHORT  [DEFAULT_SHORT_SMALL]
2SH5  SHORT  [DEFAULT_SHORT_SMALL]
2SH6  SHORT  [DEFAULT_SHORT_SMALL]
2SH7  SHORT  [DEFAULT_SHORT_SMALL]
2SH8  SHORT  [DEFAULT_SHORT_SMALL]
2SH9  SHORT  [DEFAULT_SHORT_SMALL]
2SH10  SHORT  [DEFAULT_SHORT_SMALL]
2SH11  SHORT  [DEFAULT_SHORT_SMALL]
2SH12  SHORT  [DEFAULT_SHORT_SMALL]
2SH13  SHORT  [DEFAULT_SHORT_SMALL]
2SH14  SHORT  [DEFAULT_SHORT_SMALL]
2SH15  SHORT  [DEFAULT_SHORT_SMALL]
2SH16  SHORT  [DEFAULT_SHORT_SMALL]
2SH17  SHORT  [DEFAULT_SHORT_SMALL]
2SH18  SHORT  [DEFAULT_SHORT_SMALL]
2SH19  SHORT  [DEFAULT_SHORT_SMALL]
2SH20  SHORT  [DEFAULT_SHORT_SMALL]
2TP_VDD09_CORE  TP01  [TP_040_T]
2TP_VDD_IOB_18_BOOST  TP01  [TP_040_T]
2TP_VDD_IOB_18_POR  TP01  [TP_040_T]
2TP_VDD_PLL_09  TP01  [TP_040_T]
2TP_VDD_TX_09  TP01  [TP_040_T]
2TP_VDD_TX_09_HDO  TP01  [TP_040_T]
2TP_VDD_TXPST_09  TP01  [TP_040_T]
2TP_VDDIO_18  TP01  [TP_040_T]
2TP_VDDRX_09  TP01  [TP_040_T]
2TP_VDDRX_AUX  TP01  [TP_040_T]
sheet P0031_S3_DUT
3C53  0.1U-16-X-S4-MU  [C0402]
3C54  0.1U-16-X-S4-MU  [C0402]
3C55  0.1U-16-X-S4-MU  [C0402]
3K9  UA2-5NJ-A-V3  [RL_NECUA2_5V_V3]
3K10  UA2-5NJ-A-V3  [RL_NECUA2_5V_V3]
3K48  UA2-5NJ-A-V3  [RL_NECUA2_5V_V3]
3K50  UA2-5NJ-A-V3  [RL_NECUA2_5V_V3]
3K54  G6K-2F-RF-T-5V-SPECIAL  [RL_G6K2FRT_8P_5V_GR]
3K60  G6K-2F-RF-T-5V-SPECIAL  [RL_G6K2FRT_8P_5V_GR]
3K61  G6K-2F-RF-T-5V-SPECIAL  [RL_G6K2FRT_8P_5V_GR]
3K62  G6K-2F-RF-T-5V-SPECIAL  [RL_G6K2FRT_8P_5V_GR]
3R11  49.9-1-S4  [R0402]
3R12  49.9-1-S4  [R0402]
3R13  49.9-1-S4  [R0402]
3R14  49.9-1-S4  [R0402]
3R15  49.9-1-S4  [R0402]
3R16  49.9-1-S4  [R0402]
3R17  49.9-1-S4  [R0402]
3R18  49.9-1-S4  [R0402]
3R19  49.9-1-S4  [R0402]
3R20  49.9-1-S4  [R0402]
3R21  49.9-1-S4  [R0402]
3R22  49.9-1-S4  [R0402]
3R23  49.9-1-S4  [R0402]
3R24  49.9-1-S4  [R0402]
3R25  49.9-1-S4  [R0402]
3R26  49.9-1-S4  [R0402]
3R51  NC/1M-1-S4  [R0402]
3R52  NC/1M-1-S4  [R0402]
3R53  NC/100K-1-S4  [R0402]
3R54  NC/100K-1-S4  [R0402]
3R55  100K-1-S4  [R0402]
3R161  0-5-S4  [R0402]
3R162  0-5-S4  [R0402]
3R184  50-0.1-S4-HF-VI  [R0402]
3R185  50-0.1-S4-HF-VI  [R0402]
3SW1  SW-SLIDE-1-D2.54-ECE  [SW_DIPX1_2P_H5MM]
SITE3  CU/887904-WFBGA75-10X3.5X0.636  [SK_WFBGA75P_0P65MM_JG_887904]  (sections A,B)
sheet P0032_S3_FLASH_I2C
3C1  0.1U-16-X-S4-MU  [C0402]
3K14  UA2-5NJ-A-V3  [RL_NECUA2_5V_V3]
3K15  UA2-5NJ-A-V3  [RL_NECUA2_5V_V3]
3K28  UA2-5NJ-A-V3  [RL_NECUA2_5V_V3]
3R69  NC/4.7K-1-S4  [R0402]
3R70  NC/4.7K-1-S4  [R0402]
3R71  NC/4.7K-1-S4  [R0402]
3R72  4.7K-1-S4-WA  [R0402]
3R73  NC/4.7K-1-S4  [R0402]
3R74  NC/4.7K-1-S4  [R0402]
3R147  1.1K-1-S4  [R0402]
3R148  1.1K-1-S4  [R0402]
3R163  4.7K-1-S4-WA  [R0402]
3U5  SK-SO8-1.27-LOTES-150  [SK_SO8_150_1P27MM_LOTES]
3UF1  MX25U4035FM1I-SOP8  [SOCKET_CODE]
sheet P0033_S3_POWER
3C67  1U-10-X-S4-MU  [C0402]
3C69  10U-25-X7R-SA  [C1206]
3C70  10U-25-X7R-SA  [C1206]
3C71  1U-10-X-S4-MU  [C0402]
3C73  1U-10-X-S4-MU  [C0402]
3C75  1U-10-X-S4-MU  [C0402]
3C77  1U-10-X-S4-MU  [C0402]
3C79  1U-10-X-S4-MU  [C0402]
3C81  1U-10-X-S4-MU  [C0402]
3C83  1U-10-X-S4-MU  [C0402]
3C85  1U-10-X-S4-MU  [C0402]
3C87  1U-10-X-S4-MU  [C0402]
3C89  10U-25-X7R-SA  [C1206]
3C90  10U-25-X7R-SA  [C1206]
3C91  10U-25-X7R-SA  [C1206]
3C92  10U-25-X7R-SA  [C1206]
3C93  10U-25-X7R-SA  [C1206]
3C94  10U-25-X7R-SA  [C1206]
3C95  10U-25-X7R-SA  [C1206]
3C96  10U-25-X7R-SA  [C1206]
3CA1  NC/2.2U-10-X-S4-MU  [C0402]
3CA2  NC/2.2U-10-X-S4-MU  [C0402]
3CA3  NC/2.2U-10-X-S4-MU  [C0402]
3CA4  NC/2.2U-10-X-S4-MU  [C0402]
3CA5  NC/2.2U-10-X-S4-MU  [C0402]
3CA6  NC/2.2U-10-X-S4-MU  [C0402]
3CA7  NC/2.2U-10-X-S4-MU  [C0402]
3CA8  NC/2.2U-10-X-S4-MU  [C0402]
3CA9  NC/2.2U-10-X-S4-MU  [C0402]
3CA10  NC/2.2U-10-X-S4-MU  [C0402]
3CC1  0.47U-10-X6S-S2-TY  [C0201]
3CC2  0.47U-10-X6S-S2-TY  [C0201]
3CC3  0.47U-10-X6S-S2-TY  [C0201]
3CC4  0.47U-10-X6S-S2-TY  [C0201]
3CC5  0.47U-10-X6S-S2-TY  [C0201]
3CC6  0.47U-10-X6S-S2-TY  [C0201]
3CC7  0.47U-10-X6S-S2-TY  [C0201]
3CC8  0.47U-10-X6S-S2-TY  [C0201]
3CC9  0.47U-10-X6S-S2-TY  [C0201]
3CC10  0.47U-10-X6S-S2-TY  [C0201]
3CC11  0.47U-10-X6S-S2-TY  [C0201]
3CC12  0.47U-10-X6S-S2-TY  [C0201]
3CC13  0.47U-10-X6S-S2-TY  [C0201]
3CC14  0.47U-10-X6S-S2-TY  [C0201]
3CC15  0.47U-10-X6S-S2-TY  [C0201]
3CD1  0.1U-10-X7R-S2-MU  [C0201]
3CD2  0.1U-10-X7R-S2-MU  [C0201]
3CD3  0.1U-10-X7R-S2-MU  [C0201]
3CD4  0.1U-10-X7R-S2-MU  [C0201]
3CD5  0.1U-10-X7R-S2-MU  [C0201]
3CD6  0.1U-10-X7R-S2-MU  [C0201]
3CD7  0.1U-10-X7R-S2-MU  [C0201]
3CD8  0.1U-10-X7R-S2-MU  [C0201]
3CD9  0.1U-10-X7R-S2-MU  [C0201]
3CD10  0.1U-10-X7R-S2-MU  [C0201]
3CD11  0.1U-10-X7R-S2-MU  [C0201]
3CD12  0.1U-10-X7R-S2-MU  [C0201]
3CD13  0.1U-10-X7R-S2-MU  [C0201]
3CD14  0.1U-10-X7R-S2-MU  [C0201]
3CD15  0.1U-10-X7R-S2-MU  [C0201]
3GND1  TP01  [TP_040_T]
3K55  EC2-5NJ-A  [RL_NECEC2_10P_5V]
3K56  EC2-5NJ-A  [RL_NECEC2_10P_5V]
3K57  EC2-5NJ-A  [RL_NECEC2_10P_5V]
3K58  EC2-5NJ-A  [RL_NECEC2_10P_5V]
3K59  EC2-5NJ-A  [RL_NECEC2_10P_5V]
3R200  0-5-S4  [R0402]
3R201  0-5-S4  [R0402]
3R202  0-5-S4  [R0402]
3R203  0-5-S4  [R0402]
3R204  0-5-S4  [R0402]
3R205  0-5-S4  [R0402]
3R206  0-5-S4  [R0402]
3R207  0-5-S4  [R0402]
3R208  0-5-S4  [R0402]
3R209  0-5-S4  [R0402]
3SH1  SHORT  [DEFAULT_SHORT_SMALL]
3SH2  SHORT  [DEFAULT_SHORT_SMALL]
3SH3  SHORT  [DEFAULT_SHORT_SMALL]
3SH4  SHORT  [DEFAULT_SHORT_SMALL]
3SH5  SHORT  [DEFAULT_SHORT_SMALL]
3SH6  SHORT  [DEFAULT_SHORT_SMALL]
3SH7  SHORT  [DEFAULT_SHORT_SMALL]
3SH8  SHORT  [DEFAULT_SHORT_SMALL]
3SH9  SHORT  [DEFAULT_SHORT_SMALL]
3SH10  SHORT  [DEFAULT_SHORT_SMALL]
3SH11  SHORT  [DEFAULT_SHORT_SMALL]
3SH12  SHORT  [DEFAULT_SHORT_SMALL]
3SH13  SHORT  [DEFAULT_SHORT_SMALL]
3SH14  SHORT  [DEFAULT_SHORT_SMALL]
3SH15  SHORT  [DEFAULT_SHORT_SMALL]
3SH16  SHORT  [DEFAULT_SHORT_SMALL]
3SH17  SHORT  [DEFAULT_SHORT_SMALL]
3SH18  SHORT  [DEFAULT_SHORT_SMALL]
3SH19  SHORT  [DEFAULT_SHORT_SMALL]
3SH20  SHORT  [DEFAULT_SHORT_SMALL]
3TP_VDD09_CORE  TP01  [TP_040_T]
3TP_VDD_IOB_18_BOOST  TP01  [TP_040_T]
3TP_VDD_IOB_18_POR  TP01  [TP_040_T]
3TP_VDD_PLL_09  TP01  [TP_040_T]
3TP_VDD_TX_09  TP01  [TP_040_T]
3TP_VDD_TX_09_HDO  TP01  [TP_040_T]
3TP_VDD_TXPST_09  TP01  [TP_040_T]
3TP_VDDIO_18  TP01  [TP_040_T]
3TP_VDDRX_09  TP01  [TP_040_T]
3TP_VDDRX_AUX  TP01  [TP_040_T]
sheet P0041_S4_DUT
4C53  0.1U-16-X-S4-MU  [C0402]
4C54  0.1U-16-X-S4-MU  [C0402]
4C55  0.1U-16-X-S4-MU  [C0402]
4K9  UA2-5NJ-A-V3  [RL_NECUA2_5V_V3]
4K10  UA2-5NJ-A-V3  [RL_NECUA2_5V_V3]
4K48  UA2-5NJ-A-V3  [RL_NECUA2_5V_V3]
4K50  UA2-5NJ-A-V3  [RL_NECUA2_5V_V3]
4K54  G6K-2F-RF-T-5V-SPECIAL  [RL_G6K2FRT_8P_5V_GR]
4K60  G6K-2F-RF-T-5V-SPECIAL  [RL_G6K2FRT_8P_5V_GR]
4K61  G6K-2F-RF-T-5V-SPECIAL  [RL_G6K2FRT_8P_5V_GR]
4K62  G6K-2F-RF-T-5V-SPECIAL  [RL_G6K2FRT_8P_5V_GR]
4R11  49.9-1-S4  [R0402]
4R12  49.9-1-S4  [R0402]
4R13  49.9-1-S4  [R0402]
4R14  49.9-1-S4  [R0402]
4R15  49.9-1-S4  [R0402]
4R16  49.9-1-S4  [R0402]
4R17  49.9-1-S4  [R0402]
4R18  49.9-1-S4  [R0402]
4R19  49.9-1-S4  [R0402]
4R20  49.9-1-S4  [R0402]
4R21  49.9-1-S4  [R0402]
4R22  49.9-1-S4  [R0402]
4R23  49.9-1-S4  [R0402]
4R24  49.9-1-S4  [R0402]
4R25  49.9-1-S4  [R0402]
4R26  49.9-1-S4  [R0402]
4R51  NC/1M-1-S4  [R0402]
4R52  NC/1M-1-S4  [R0402]
4R53  NC/100K-1-S4  [R0402]
4R54  NC/100K-1-S4  [R0402]
4R55  100K-1-S4  [R0402]
4R161  0-5-S4  [R0402]
4R162  0-5-S4  [R0402]
4R184  50-0.1-S4-HF-VI  [R0402]
4R185  50-0.1-S4-HF-VI  [R0402]
4SW1  SW-SLIDE-1-D2.54-ECE  [SW_DIPX1_2P_H5MM]
SITE4  CU/887904-WFBGA75-10X3.5X0.636  [SK_WFBGA75P_0P65MM_JG_887904]  (sections A,B)
sheet P0042_S4_FLASH_I2C
4C1  0.1U-16-X-S4-MU  [C0402]
4K14  UA2-5NJ-A-V3  [RL_NECUA2_5V_V3]
4K15  UA2-5NJ-A-V3  [RL_NECUA2_5V_V3]
4K28  UA2-5NJ-A-V3  [RL_NECUA2_5V_V3]
4R69  NC/4.7K-1-S4  [R0402]
4R70  NC/4.7K-1-S4  [R0402]
4R71  NC/4.7K-1-S4  [R0402]
4R72  4.7K-1-S4-WA  [R0402]
4R73  NC/4.7K-1-S4  [R0402]
4R74  NC/4.7K-1-S4  [R0402]
4R147  1.1K-1-S4  [R0402]
4R148  1.1K-1-S4  [R0402]
4R163  4.7K-1-S4-WA  [R0402]
4U5  SK-SO8-1.27-LOTES-150  [SK_SO8_150_1P27MM_LOTES]
4UF1  MX25U4035FM1I-SOP8  [SOCKET_CODE]
sheet P0043_S4_POWER
4C67  1U-10-X-S4-MU  [C0402]
4C69  10U-25-X7R-SA  [C1206]
4C70  10U-25-X7R-SA  [C1206]
4C71  1U-10-X-S4-MU  [C0402]
4C73  1U-10-X-S4-MU  [C0402]
4C75  1U-10-X-S4-MU  [C0402]
4C77  1U-10-X-S4-MU  [C0402]
4C79  1U-10-X-S4-MU  [C0402]
4C81  1U-10-X-S4-MU  [C0402]
4C83  1U-10-X-S4-MU  [C0402]
4C85  1U-10-X-S4-MU  [C0402]
4C87  1U-10-X-S4-MU  [C0402]
4C89  10U-25-X7R-SA  [C1206]
4C90  10U-25-X7R-SA  [C1206]
4C91  10U-25-X7R-SA  [C1206]
4C92  10U-25-X7R-SA  [C1206]
4C93  10U-25-X7R-SA  [C1206]
4C94  10U-25-X7R-SA  [C1206]
4C95  10U-25-X7R-SA  [C1206]
4C96  10U-25-X7R-SA  [C1206]
4CA1  NC/2.2U-10-X-S4-MU  [C0402]
4CA2  NC/2.2U-10-X-S4-MU  [C0402]
4CA3  NC/2.2U-10-X-S4-MU  [C0402]
4CA4  NC/2.2U-10-X-S4-MU  [C0402]
4CA5  NC/2.2U-10-X-S4-MU  [C0402]
4CA6  NC/2.2U-10-X-S4-MU  [C0402]
4CA7  NC/2.2U-10-X-S4-MU  [C0402]
4CA8  NC/2.2U-10-X-S4-MU  [C0402]
4CA9  NC/2.2U-10-X-S4-MU  [C0402]
4CA10  NC/2.2U-10-X-S4-MU  [C0402]
4CC1  0.47U-10-X6S-S2-TY  [C0201]
4CC2  0.47U-10-X6S-S2-TY  [C0201]
4CC3  0.47U-10-X6S-S2-TY  [C0201]
4CC4  0.47U-10-X6S-S2-TY  [C0201]
4CC5  0.47U-10-X6S-S2-TY  [C0201]
4CC6  0.47U-10-X6S-S2-TY  [C0201]
4CC7  0.47U-10-X6S-S2-TY  [C0201]
4CC8  0.47U-10-X6S-S2-TY  [C0201]
4CC9  0.47U-10-X6S-S2-TY  [C0201]
4CC10  0.47U-10-X6S-S2-TY  [C0201]
4CC11  0.47U-10-X6S-S2-TY  [C0201]
4CC12  0.47U-10-X6S-S2-TY  [C0201]
4CC13  0.47U-10-X6S-S2-TY  [C0201]
4CC14  0.47U-10-X6S-S2-TY  [C0201]
4CC15  0.47U-10-X6S-S2-TY  [C0201]
4CD1  0.1U-10-X7R-S2-MU  [C0201]
4CD2  0.1U-10-X7R-S2-MU  [C0201]
4CD3  0.1U-10-X7R-S2-MU  [C0201]
4CD4  0.1U-10-X7R-S2-MU  [C0201]
4CD5  0.1U-10-X7R-S2-MU  [C0201]
4CD6  0.1U-10-X7R-S2-MU  [C0201]
4CD7  0.1U-10-X7R-S2-MU  [C0201]
4CD8  0.1U-10-X7R-S2-MU  [C0201]
4CD9  0.1U-10-X7R-S2-MU  [C0201]
4CD10  0.1U-10-X7R-S2-MU  [C0201]
4CD11  0.1U-10-X7R-S2-MU  [C0201]
4CD12  0.1U-10-X7R-S2-MU  [C0201]
4CD13  0.1U-10-X7R-S2-MU  [C0201]
4CD14  0.1U-10-X7R-S2-MU  [C0201]
4CD15  0.1U-10-X7R-S2-MU  [C0201]
4GND1  TP01  [TP_040_T]
4K55  EC2-5NJ-A  [RL_NECEC2_10P_5V]
4K56  EC2-5NJ-A  [RL_NECEC2_10P_5V]
4K57  EC2-5NJ-A  [RL_NECEC2_10P_5V]
4K58  EC2-5NJ-A  [RL_NECEC2_10P_5V]
4K59  EC2-5NJ-A  [RL_NECEC2_10P_5V]
4R200  0-5-S4  [R0402]
4R201  0-5-S4  [R0402]
4R202  0-5-S4  [R0402]
4R203  0-5-S4  [R0402]
4R204  0-5-S4  [R0402]
4R205  0-5-S4  [R0402]
4R206  0-5-S4  [R0402]
4R207  0-5-S4  [R0402]
4R208  0-5-S4  [R0402]
4R209  0-5-S4  [R0402]
4SH1  SHORT  [DEFAULT_SHORT_SMALL]
4SH2  SHORT  [DEFAULT_SHORT_SMALL]
4SH3  SHORT  [DEFAULT_SHORT_SMALL]
4SH4  SHORT  [DEFAULT_SHORT_SMALL]
4SH5  SHORT  [DEFAULT_SHORT_SMALL]
4SH6  SHORT  [DEFAULT_SHORT_SMALL]
4SH7  SHORT  [DEFAULT_SHORT_SMALL]
4SH8  SHORT  [DEFAULT_SHORT_SMALL]
4SH9  SHORT  [DEFAULT_SHORT_SMALL]
4SH10  SHORT  [DEFAULT_SHORT_SMALL]
4SH11  SHORT  [DEFAULT_SHORT_SMALL]
4SH12  SHORT  [DEFAULT_SHORT_SMALL]
4SH13  SHORT  [DEFAULT_SHORT_SMALL]
4SH14  SHORT  [DEFAULT_SHORT_SMALL]
4SH15  SHORT  [DEFAULT_SHORT_SMALL]
4SH16  SHORT  [DEFAULT_SHORT_SMALL]
4SH17  SHORT  [DEFAULT_SHORT_SMALL]
4SH18  SHORT  [DEFAULT_SHORT_SMALL]
4SH19  SHORT  [DEFAULT_SHORT_SMALL]
4SH20  SHORT  [DEFAULT_SHORT_SMALL]
4TP_VDD09_CORE  TP01  [TP_040_T]
4TP_VDD_IOB_18_BOOST  TP01  [TP_040_T]
4TP_VDD_IOB_18_POR  TP01  [TP_040_T]
4TP_VDD_PLL_09  TP01  [TP_040_T]
4TP_VDD_TX_09  TP01  [TP_040_T]
4TP_VDD_TX_09_HDO  TP01  [TP_040_T]
4TP_VDD_TXPST_09  TP01  [TP_040_T]
4TP_VDDIO_18  TP01  [TP_040_T]
4TP_VDDRX_09  TP01  [TP_040_T]
4TP_VDDRX_AUX  TP01  [TP_040_T]

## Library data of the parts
2C1 2C53-2C55 3C1 3C53-3C55 4C1 4C53-4C55 = 0.1U-16-X-S4-MU
2K9 2K10 2K14 2K15 2K28 2K48 2K50 3K9 3K10 3K14 3K15 3K28 3K48 3K50 4K9 4K10 4K14 4K15 4K28 4K48 4K50 = UA2-5NJ-A-V3
2K54 2K60-2K62 3K54 3K60-3K62 4K54 4K60-4K62 = G6K-2F-RF-T-5V-SPECIAL
2R11-2R26 3R11-3R26 4R11-4R26 = 49.9-1-S4
2R51 2R52 3R51 3R52 4R51 4R52 = 1M-1-S4
2R53-2R55 3R53-3R55 4R53-4R55 = 100K-1-S4
2R161 2R162 2R200-2R209 3R161 3R162 3R200-3R209 4R161 4R162 4R200-4R209 = 0-5-S4
2R184 2R185 3R184 3R185 4R184 4R185 = 50-0.1-S4-HF-VI
2SW1 3SW1 4SW1 = SW-SLIDE-1-D2.54-ECE
SITE2-SITE4 = CU_887904-WFBGA75-10X3.5X0.636
2R69-2R74 2R163 3R69-3R74 3R163 4R69-4R74 4R163 = 4.7K-1-S4-WA
2R147 2R148 3R147 3R148 4R147 4R148 = 1.1K-1-S4
2U5 3U5 4U5 = MX25V4006EM1I-13G-SO8
2UF1 3UF1 4UF1 = REF-CODE-FLASH
2C67 2C71 2C73 2C75 2C77 2C79 2C81 2C83 2C85 2C87 3C67 3C71 3C73 3C75 3C77 3C79 3C81 3C83 3C85 3C87 4C67 4C71 4C73 4C75 4C77 4C79 4C81 4C83 4C85 4C87 = 1U-10-X-S4-MU
2C69 2C70 2C89-2C96 3C69 3C70 3C89-3C96 4C69 4C70 4C89-4C96 = 10U-25-X7R-SA
2CA1-2CA10 3CA1-3CA10 4CA1-4CA10 = 2.2U-10-X-S4-MU
2CC1-2CC15 3CC1-3CC15 4CC1-4CC15 = 0.47U-10-X6S-S2-TY
2CD1-2CD15 3CD1-3CD15 4CD1-4CD15 = 0.1U-10-X7R-S2-MU
2GND1 2TP_VDD09_CORE 2TP_VDD_IOB_18_BOOST 2TP_VDD_IOB_18_POR 2TP_VDD_PLL_09 2TP_VDD_TX_09 2TP_VDD_TX_09_HDO 2TP_VDD_TXPST_09 2TP_VDDIO_18 2TP_VDDRX_09 2TP_VDDRX_AUX 3GND1 3TP_VDD09_CORE 3TP_VDD_IOB_18_BOOST 3TP_VDD_IOB_18_POR 3TP_VDD_PLL_09 3TP_VDD_TX_09 3TP_VDD_TX_09_HDO 3TP_VDD_TXPST_09 3TP_VDDIO_18 3TP_VDDRX_09 3TP_VDDRX_AUX 4GND1 4TP_VDD09_CORE 4TP_VDD_IOB_18_BOOST 4TP_VDD_IOB_18_POR 4TP_VDD_PLL_09 4TP_VDD_TX_09 4TP_VDD_TX_09_HDO 4TP_VDD_TXPST_09 4TP_VDDIO_18 4TP_VDDRX_09 4TP_VDDRX_AUX = TP01
2K55-2K59 3K55-3K59 4K55-4K59 = EC2-5NJ-A
2SH1-2SH20 3SH1-3SH20 4SH1-4SH20 = SHORT

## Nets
GND: 2C1.2 2C55.1 2C67.2 2C69.2 2C70.2 2C71.2 2C73.2 2C75.2 2C77.2 2C79.2 2C81.2 2C83.2 2C85.2 2C87.2 2C89.2 2C90.2 2C91.2 2C92.2 2C93.2 2C94.2 2C95.2 2C96.2 2CA1.2 2CA2.2 2CA3.2 2CA4.2 2CA5.2 2CA6.2 2CA7.2 2CA8.2 2CA9.2 2CA10.2 2CC1.2 2CC2.2 2CC3.2 2CC4.2 2CC5.2 2CC6.2 2CC7.2 2CC8.2 2CC9.2 2CC10.2 2CC11.2 2CC12.2 2CC13.2 2CC14.2 2CC15.2 2CD1.2 2CD2.2 2CD3.2 2CD4.2 2CD5.2 2CD6.2 2CD7.2 2CD8.2 2CD9.2 2CD10.2 2CD11.2 2CD12.2 2CD13.2 2CD14.2 2CD15.2 2GND1.1(TP) 2K54.G1 2K54.G2 2K54.G3 2K54.G4 2K54.G5 2K54.G6 2K54.G7 2K54.G8 2K54.G9 2K54.G10 2K60.G1 2K60.G2 2K60.G3 2K60.G4 2K60.G5 2K60.G6 2K60.G7 2K60.G8 2K60.G9 2K60.G10 2K61.G1 2K61.G2 2K61.G3 2K61.G4 2K61.G5 2K61.G6 2K61.G7 2K61.G8 2K61.G9 2K61.G10 2K62.G1 2K62.G2 2K62.G3 2K62.G4 2K62.G5 2K62.G6 2K62.G7 2K62.G8 2K62.G9 2K62.G10 2R51.1 2R54.1 2R163.1 2R184.2 2R185.2 2SH2.2 2SH4.2 2SH5.2 2SH8.2 2SH9.2 2SH11.2 2SH13.2 2SH15.2 2SH17.2 2SH19.2 2U5.4(GND) 3C1.2 3C55.1 3C67.2 3C69.2 3C70.2 3C71.2 3C73.2 3C75.2 3C77.2 3C79.2 3C81.2 3C83.2 3C85.2 3C87.2 3C89.2 3C90.2 3C91.2 3C92.2 3C93.2 3C94.2 3C95.2 3C96.2 3CA1.2 3CA2.2 3CA3.2 3CA4.2 3CA5.2 3CA6.2 3CA7.2 3CA8.2 3CA9.2 3CA10.2 3CC1.2 3CC2.2 3CC3.2 3CC4.2 3CC5.2 3CC6.2 3CC7.2 3CC8.2 3CC9.2 3CC10.2 3CC11.2 3CC12.2 3CC13.2 3CC14.2 3CC15.2 3CD1.2 3CD2.2 3CD3.2 3CD4.2 3CD5.2 3CD6.2 3CD7.2 3CD8.2 3CD9.2 3CD10.2 3CD11.2 3CD12.2 3CD13.2 3CD14.2 3CD15.2 3GND1.1(TP) 3K54.G1 3K54.G2 3K54.G3 3K54.G4 3K54.G5 3K54.G6 3K54.G7 3K54.G8 3K54.G9 3K54.G10 3K60.G1 3K60.G2 3K60.G3 3K60.G4 3K60.G5 3K60.G6 3K60.G7 3K60.G8 3K60.G9 3K60.G10 3K61.G1 3K61.G2 3K61.G3 3K61.G4 3K61.G5 3K61.G6 3K61.G7 3K61.G8 3K61.G9 3K61.G10 3K62.G1 3K62.G2 3K62.G3 3K62.G4 3K62.G5 3K62.G6 3K62.G7 3K62.G8 3K62.G9 3K62.G10 3R51.1 3R54.1 3R163.1 3R184.2 3R185.2 3SH2.2 3SH4.2 3SH5.2 3SH8.2 3SH9.2 3SH11.2 3SH13.2 3SH15.2 3SH17.2 3SH19.2 3U5.4(GND) 4C1.2 4C55.1 4C67.2 4C69.2 4C70.2 4C71.2 4C73.2 4C75.2 4C77.2 4C79.2 4C81.2 4C83.2 4C85.2 4C87.2 4C89.2 4C90.2 4C91.2 4C92.2 4C93.2 4C94.2 4C95.2 4C96.2 4CA1.2 4CA2.2 4CA3.2 4CA4.2 4CA5.2 4CA6.2 4CA7.2 4CA8.2 4CA9.2 4CA10.2 4CC1.2 4CC2.2 4CC3.2 4CC4.2 4CC5.2 4CC6.2 4CC7.2 4CC8.2 4CC9.2 4CC10.2 4CC11.2 4CC12.2 4CC13.2 4CC14.2 4CC15.2 4CD1.2 4CD2.2 4CD3.2 4CD4.2 4CD5.2 4CD6.2 4CD7.2 4CD8.2 4CD9.2 4CD10.2 4CD11.2 4CD12.2 4CD13.2 4CD14.2 4CD15.2 4GND1.1(TP) 4K54.G1 4K54.G2 4K54.G3 4K54.G4 4K54.G5 4K54.G6 4K54.G7 4K54.G8 4K54.G9 4K54.G10 4K60.G1 4K60.G2 4K60.G3 4K60.G4 4K60.G5 4K60.G6 4K60.G7 4K60.G8 4K60.G9 4K60.G10 4K61.G1 4K61.G2 4K61.G3 4K61.G4 4K61.G5 4K61.G6 4K61.G7 4K61.G8 4K61.G9 4K61.G10 4K62.G1 4K62.G2 4K62.G3 4K62.G4 4K62.G5 4K62.G6 4K62.G7 4K62.G8 4K62.G9 4K62.G10 4R51.1 4R54.1 4R163.1 4R184.2 4R185.2 4SH2.2 4SH4.2 4SH5.2 4SH8.2 4SH9.2 4SH11.2 4SH13.2 4SH15.2 4SH17.2 4SH19.2 4U5.4(GND) SITE2.B4(VSS_CORE_09[1]) SITE2.B5(VSS_CORE_09[2]) SITE2.C12(VSS_CORE_09[3]) SITE2.C13(VSS_CORE_09[4]) SITE3.B4(VSS_CORE_09[1]) SITE3.B5(VSS_CORE_09[2]) SITE3.C12(VSS_CORE_09[3]) SITE3.C13(VSS_CORE_09[4]) SITE4.B4(VSS_CORE_09[1]) SITE4.B5(VSS_CORE_09[2]) SITE4.C12(VSS_CORE_09[3]) SITE4.C13(VSS_CORE_09[4]) ; also on sheet 12 13 14 15 16 17 18 19 20 21 22 23 24
S2_AUX1+: 2K9.5 2R162.1
S2_AUX1-: 2K9.4 2R161.1
S2_AUX2+: 2C54.2 2R52.1 2R54.2 2R162.2
S2_AUX2-: 2C53.2 2R51.2 2R53.2 2R161.2
S2_AUX+: 2K9.6 2K50.6 SITE2.D14(AUX_P)
S2_AUX-: 2K9.3 2K50.3 SITE2.E14(AUX_N)
S2_AUX_100DCH001+: 2K9.7
S2_AUX_100DCH001-: 2K9.2
S2_AUX_100DCH003+: 2C54.1
S2_AUX_100DCH003-: 2C53.1
S2_DCH005: SITE2.A14(HPD)
S2_DCH006: 2K10.3 SITE2.A1(RESET)
S2_DCH007: SITE2.B15(BIST)
S2_DCH009: SITE2.C15(CABC_EN)
S2_DCH010: SITE2.A15(PWMI)
S2_DCH011: SITE2.E3(PWMO)
S2_DCH012: 2K28.6 SITE2.C1(I2C_SDA)
S2_DCH013: 2K28.3 SITE2.D1(I2C_SCL)
S2_DCH014: 2K48.2
S2_DCH015: SITE2.E5(GPIO1)
S2_DCH016: SITE2.D5(GPIO2)
S2_DCH017: SITE2.D6(GPIO3)
S2_DCH018: SITE2.D7(GPIO4)
S2_DCH019: SITE2.D8(GPIO5)
S2_DCH020: SITE2.E6(GPIO6)
S2_DCH021: SITE2.D3(GPIO7)
S2_DCH022: SITE2.E4(GPIO8)
S2_DCH023: SITE2.C2(GPIO9)
S2_DCH024: SITE2.D15(GPIO10)
S2_DCH025: SITE2.B1(STV1)
S2_DCH026: SITE2.D2(STV2)
S2_DCH027: SITE2.B2(CPV)
S2_DCH028: SITE2.E1(OE1)
S2_DCH029: SITE2.E2(OE2)
S2_DCH030: SITE2.A3(XSTB)
S2_DCH031: SITE2.A2(SD_LOCK)
S2_DCH032: 2R200.2
S2_DCH033: 2R201.2
S2_DCH034: 2R202.2
S2_DCH035: 2R203.2
S2_DCH036: 2R204.2
S2_DCH037: 2R205.2
S2_DCH038: 2R206.2
S2_DCH039: 2R207.2
S2_DCH040: 2R208.2
S2_DCH041: 2R209.2
S2_DCH42: 2K15.2
S2_DCH43: 2K15.7
S2_DCH44: 2K14.2
S2_DCH45: 2K14.7
S2_DPS_F01: 2C67.1 2CA1.1 2CC1.1 2CC2.1 2CC3.1 2CC4.1 2CD1.1 2CD2.1 2CD3.1 2CD4.1 2K55.4 2R200.1 2SH1.2 2TP_VDD09_CORE.1(TP) SITE2.C4(VDD_CORE_09[1]) SITE2.C8(VDD_CORE_09[2]) SITE2.C9(VDD_CORE_09[3]) SITE2.C10(VDD_CORE_09[4])
S2_DPS_F03: 2C71.1 2CA2.1 2CC5.1 2CC6.1 2CC7.1 2CD5.1 2CD6.1 2CD7.1 2K56.4 2R55.2 2R201.1 2SH3.2 2TP_VDDIO_18.1(TP) SITE2.C5(VDD_IO_18[2]) SITE2.C6(VDD_IO_18[3]) SITE2.C11(VDD_IO_18[1])
S2_DPS_F04: 2C73.1 2CA3.1 2CC8.1 2CD8.1 2K57.9 2R202.1 2SH6.2 2TP_VDD_TX_09_HDO.1(TP) SITE2.A5(VDD_TX_09_HDO)
S2_DPS_F05: 2C75.1 2CA4.1 2CC9.1 2CD9.1 2K58.4 2R203.1 2SH7.2 2TP_VDD_TXPST_09.1(TP) SITE2.C7(VDD_TXPST_09)
S2_DPS_F06: 2C77.1 2CA5.1 2CC10.1 2CD10.1 2K58.9 2R204.1 2SH10.2 2TP_VDD_TX_09.1(TP) SITE2.A4(VDD_TX_09)
S2_DPS_F07: 2C79.1 2CA6.1 2CC11.1 2CD11.1 2K59.4 2R205.1 2SH12.2 2TP_VDDRX_AUX.1(TP) SITE2.C14(VDDRX_AUX_09)
S2_DPS_F08: 2C81.1 2CA7.1 2CC12.1 2CD12.1 2K56.9 2R206.1 2SH14.2 2TP_VDDRX_09.1(TP) SITE2.E15(VDDRX_09)
S2_DPS_F09: 2C83.1 2CA8.1 2CC13.1 2CD13.1 2K59.9 2R207.1 2SH16.2 2TP_VDD_PLL_09.1(TP) SITE2.B3(VDD_PLL_09)
S2_DPS_F10: 2C85.1 2CA9.1 2CC14.1 2CD14.1 2K55.9 2R208.1 2SH18.2 2TP_VDD_IOB_18_BOOST.1(TP) SITE2.B14(VDD_IOB_18_BOOST)
S2_DPS_F11: 2C87.1 2CA10.1 2CC15.1 2CD15.1 2K57.4 2R209.1 2SH20.2 2TP_VDD_IOB_18_POR.1(TP) SITE2.C3(VDD_IOB_18_POR)
S2_DPS_FS01: 2SH1.1
S2_DPS_FS03: 2SH3.1
S2_DPS_FS04: 2SH6.1
S2_DPS_FS05: 2SH7.1
S2_DPS_FS06: 2SH10.1
S2_DPS_FS07: 2SH12.1
S2_DPS_FS08: 2SH14.1
S2_DPS_FS09: 2SH16.1
S2_DPS_FS10: 2SH18.1
S2_DPS_FS11: 2SH20.1
S2_DPS_GS01: 2SH2.1
S2_DPS_GS03: 2SH4.1
S2_DPS_GS04: 2SH5.1
S2_DPS_GS05: 2SH8.1
S2_DPS_GS06: 2SH9.1
S2_DPS_GS07: 2SH11.1
S2_DPS_GS08: 2SH13.1
S2_DPS_GS09: 2SH15.1
S2_DPS_GS10: 2SH17.1
S2_DPS_GS11: 2SH19.1
S2_RLY01: 2K9.8(V-)
S2_RLY02: 2K50.8(V-)
S2_RLY03: 2K10.8(V-)
S2_RLY04: 2K48.8(V-)
S2_RLY08: 2K54.8(V-)
S2_RLY09: 2K61.8(V-)
S2_RLY20: 2K55.12(V-)
S2_RLY22: 2K57.12(V-)
S2_RLY24: 2K59.12(V-)
S2_RLY27: 2K15.8(V-)
S2_RLY43: 2K60.8(V-)
S2_RLY44: 2K62.8(V-)
S2_RLY45: 2K14.8(V-)
S2_RLY46: 2K28.8(V-)
S2_RLY47: 2K56.12(V-)
S2_RLY48: 2K58.12(V-)
S2_ROM_SPI_CS: 2K15.6 SITE2.E7(ROM_SPI_CS)
S2_ROM_SPI_SCK: 2K15.3 SITE2.E8(ROM_SPI_SCK)
S2_ROM_SPI_SDI: 2K14.6 SITE2.E9(ROM_SPI_SDI)
S2_ROM_SPI_SDO: 2K14.3 SITE2.D9(ROM_SPI_SDO)
S2_RX_85DCH00+: SITE2.E10(RX_N0)
S2_RX_85DCH00-: SITE2.D10(RX_P0)
S2_RX_85DCH01+: SITE2.E11(RX_N1)
S2_RX_85DCH01-: SITE2.D11(RX_P1)
S2_RX_85DCH02+: SITE2.D12(RX_N2)
S2_RX_85DCH02-: SITE2.E12(RX_P2)
S2_RX_85DCH03+: SITE2.D13(RX_N3)
S2_RX_85DCH03-: SITE2.E13(RX_P3)
S2_SPI_1_CSN: 2K15.5 2R69.2 2U5.1(CS#)
S2_SPI_1_SCK: 2K15.4 2R73.2 2U5.6(SCLK)
S2_SPI_1_SDI: 2K14.5 2R70.2 2U5.2(SO)
S2_SPI_1_SDO: 2K14.4 2R74.2 2U5.5(SI)
S2_TEST: 2K48.3 SITE2.D4(TEST)
S2_TX_100DCH0_N: 2R11.1 SITE2.A13(TX0_N)
S2_TX_100DCH0_P: 2R12.2 SITE2.B13(TX0_P)
S2_TX_100DCH1_N: 2R13.1 SITE2.B12(TX1_N)
S2_TX_100DCH1_P: 2R14.2 SITE2.A12(TX1_P)
S2_TX_100DCH2_N: 2R15.1 SITE2.B11(TX2_N)
S2_TX_100DCH2_P: 2R16.2 SITE2.A11(TX2_P)
S2_TX_100DCH3_N: 2R17.1 SITE2.B10(TX3_N)
S2_TX_100DCH3_P: 2R18.2 SITE2.A10(TX3_P)
S2_TX_100DCH4_N: 2R19.1 SITE2.A9(TX4_N)
S2_TX_100DCH4_P: 2R20.2 SITE2.B9(TX4_P)
S2_TX_100DCH5_N: 2R21.1 SITE2.A8(TX5_N)
S2_TX_100DCH5_P: 2R22.2 SITE2.B8(TX5_P)
S2_TX_100DCH6_N: 2R23.1 SITE2.A7(TX6_N)
S2_TX_100DCH6_P: 2R24.2 SITE2.B7(TX6_P)
S2_TX_100DCH7_N: 2R25.1 SITE2.B6(TX7_N)
S2_TX_100DCH7_P: 2R26.2 SITE2.A6(TX7_P)
S2_V25: 2R52.2 2R53.1
S2_VCC_I2C_Flash_18: 2C1.1 2R69.1 2R70.1 2R71.1 2R72.1 2R73.1 2R74.1 2R147.2 2R148.2 2U5.8(VCC)
S2_VDD_efuse_power: 2K48.4
S3_AUX1+: 3K9.5 3R162.1
S3_AUX1-: 3K9.4 3R161.1
S3_AUX2+: 3C54.2 3R52.1 3R54.2 3R162.2
S3_AUX2-: 3C53.2 3R51.2 3R53.2 3R161.2
S3_AUX+: 3K9.6 3K50.6 SITE3.D14(AUX_P)
S3_AUX-: 3K9.3 3K50.3 SITE3.E14(AUX_N)
S3_AUX_100DCH001+: 3K9.7
S3_AUX_100DCH001-: 3K9.2
S3_AUX_100DCH003+: 3C54.1
S3_AUX_100DCH003-: 3C53.1
S3_DCH005: SITE3.A14(HPD)
S3_DCH006: 3K10.3 SITE3.A1(RESET)
S3_DCH007: SITE3.B15(BIST)
S3_DCH009: SITE3.C15(CABC_EN)
S3_DCH010: SITE3.A15(PWMI)
S3_DCH011: SITE3.E3(PWMO)
S3_DCH012: 3K28.6 SITE3.C1(I2C_SDA)
S3_DCH013: 3K28.3 SITE3.D1(I2C_SCL)
S3_DCH014: 3K48.2
S3_DCH015: SITE3.E5(GPIO1)
S3_DCH016: SITE3.D5(GPIO2)
S3_DCH017: SITE3.D6(GPIO3)
S3_DCH018: SITE3.D7(GPIO4)
S3_DCH019: SITE3.D8(GPIO5)
S3_DCH020: SITE3.E6(GPIO6)
S3_DCH021: SITE3.D3(GPIO7)
S3_DCH022: SITE3.E4(GPIO8)
S3_DCH023: SITE3.C2(GPIO9)
S3_DCH024: SITE3.D15(GPIO10)
S3_DCH025: SITE3.B1(STV1)
S3_DCH026: SITE3.D2(STV2)
S3_DCH027: SITE3.B2(CPV)
S3_DCH028: SITE3.E1(OE1)
S3_DCH029: SITE3.E2(OE2)
S3_DCH030: SITE3.A3(XSTB)
S3_DCH031: SITE3.A2(SD_LOCK)
S3_DCH032: 3R200.2
S3_DCH033: 3R201.2
S3_DCH034: 3R202.2
S3_DCH035: 3R203.2
S3_DCH036: 3R204.2
S3_DCH037: 3R205.2
S3_DCH038: 3R206.2
S3_DCH039: 3R207.2
S3_DCH040: 3R208.2
S3_DCH041: 3R209.2
S3_DCH42: 3K15.2
S3_DCH43: 3K15.7
S3_DCH44: 3K14.2
S3_DCH45: 3K14.7
S3_DPS_F01: 3C67.1 3CA1.1 3CC1.1 3CC2.1 3CC3.1 3CC4.1 3CD1.1 3CD2.1 3CD3.1 3CD4.1 3K55.4 3R200.1 3SH1.2 3TP_VDD09_CORE.1(TP) SITE3.C4(VDD_CORE_09[1]) SITE3.C8(VDD_CORE_09[2]) SITE3.C9(VDD_CORE_09[3]) SITE3.C10(VDD_CORE_09[4])
S3_DPS_F03: 3C71.1 3CA2.1 3CC5.1 3CC6.1 3CC7.1 3CD5.1 3CD6.1 3CD7.1 3K56.4 3R55.2 3R201.1 3SH3.2 3TP_VDDIO_18.1(TP) SITE3.C5(VDD_IO_18[2]) SITE3.C6(VDD_IO_18[3]) SITE3.C11(VDD_IO_18[1])
S3_DPS_F04: 3C73.1 3CA3.1 3CC8.1 3CD8.1 3K57.9 3R202.1 3SH6.2 3TP_VDD_TX_09_HDO.1(TP) SITE3.A5(VDD_TX_09_HDO)
S3_DPS_F05: 3C75.1 3CA4.1 3CC9.1 3CD9.1 3K58.4 3R203.1 3SH7.2 3TP_VDD_TXPST_09.1(TP) SITE3.C7(VDD_TXPST_09)
S3_DPS_F06: 3C77.1 3CA5.1 3CC10.1 3CD10.1 3K58.9 3R204.1 3SH10.2 3TP_VDD_TX_09.1(TP) SITE3.A4(VDD_TX_09)
S3_DPS_F07: 3C79.1 3CA6.1 3CC11.1 3CD11.1 3K59.4 3R205.1 3SH12.2 3TP_VDDRX_AUX.1(TP) SITE3.C14(VDDRX_AUX_09)
S3_DPS_F08: 3C81.1 3CA7.1 3CC12.1 3CD12.1 3K56.9 3R206.1 3SH14.2 3TP_VDDRX_09.1(TP) SITE3.E15(VDDRX_09)
S3_DPS_F09: 3C83.1 3CA8.1 3CC13.1 3CD13.1 3K59.9 3R207.1 3SH16.2 3TP_VDD_PLL_09.1(TP) SITE3.B3(VDD_PLL_09)
S3_DPS_F10: 3C85.1 3CA9.1 3CC14.1 3CD14.1 3K55.9 3R208.1 3SH18.2 3TP_VDD_IOB_18_BOOST.1(TP) SITE3.B14(VDD_IOB_18_BOOST)
S3_DPS_F11: 3C87.1 3CA10.1 3CC15.1 3CD15.1 3K57.4 3R209.1 3SH20.2 3TP_VDD_IOB_18_POR.1(TP) SITE3.C3(VDD_IOB_18_POR)
S3_DPS_FS01: 3SH1.1
S3_DPS_FS03: 3SH3.1
S3_DPS_FS04: 3SH6.1
S3_DPS_FS05: 3SH7.1
S3_DPS_FS06: 3SH10.1
S3_DPS_FS07: 3SH12.1
S3_DPS_FS08: 3SH14.1
S3_DPS_FS09: 3SH16.1
S3_DPS_FS10: 3SH18.1
S3_DPS_FS11: 3SH20.1
S3_DPS_GS01: 3SH2.1
S3_DPS_GS03: 3SH4.1
S3_DPS_GS04: 3SH5.1
S3_DPS_GS05: 3SH8.1
S3_DPS_GS06: 3SH9.1
S3_DPS_GS07: 3SH11.1
S3_DPS_GS08: 3SH13.1
S3_DPS_GS09: 3SH15.1
S3_DPS_GS10: 3SH17.1
S3_DPS_GS11: 3SH19.1
S3_RLY01: 3K9.8(V-)
S3_RLY02: 3K50.8(V-)
S3_RLY03: 3K10.8(V-)
S3_RLY04: 3K48.8(V-)
S3_RLY08: 3K54.8(V-)
S3_RLY09: 3K61.8(V-)
S3_RLY20: 3K55.12(V-)
S3_RLY22: 3K57.12(V-)
S3_RLY24: 3K59.12(V-)
S3_RLY27: 3K15.8(V-)
S3_RLY43: 3K60.8(V-)
S3_RLY44: 3K62.8(V-)
S3_RLY45: 3K14.8(V-)
S3_RLY46: 3K28.8(V-)
S3_RLY47: 3K56.12(V-)
S3_RLY48: 3K58.12(V-)
S3_ROM_SPI_CS: 3K15.6 SITE3.E7(ROM_SPI_CS)
S3_ROM_SPI_SCK: 3K15.3 SITE3.E8(ROM_SPI_SCK)
S3_ROM_SPI_SDI: 3K14.6 SITE3.E9(ROM_SPI_SDI)
S3_ROM_SPI_SDO: 3K14.3 SITE3.D9(ROM_SPI_SDO)
S3_RX_85DCH00+: SITE3.E10(RX_N0)
S3_RX_85DCH00-: SITE3.D10(RX_P0)
S3_RX_85DCH01+: SITE3.E11(RX_N1)
S3_RX_85DCH01-: SITE3.D11(RX_P1)
S3_RX_85DCH02+: SITE3.D12(RX_N2)
S3_RX_85DCH02-: SITE3.E12(RX_P2)
S3_RX_85DCH03+: SITE3.D13(RX_N3)
S3_RX_85DCH03-: SITE3.E13(RX_P3)
S3_SPI_1_CSN: 3K15.5 3R69.2 3U5.1(CS#)
S3_SPI_1_SCK: 3K15.4 3R73.2 3U5.6(SCLK)
S3_SPI_1_SDI: 3K14.5 3R70.2 3U5.2(SO)
S3_SPI_1_SDO: 3K14.4 3R74.2 3U5.5(SI)
S3_TEST: 3K48.3 SITE3.D4(TEST)
S3_TX_100DCH0_N: 3R11.1 SITE3.A13(TX0_N)
S3_TX_100DCH0_P: 3R12.2 SITE3.B13(TX0_P)
S3_TX_100DCH1_N: 3R13.1 SITE3.B12(TX1_N)
S3_TX_100DCH1_P: 3R14.2 SITE3.A12(TX1_P)
S3_TX_100DCH2_N: 3R15.1 SITE3.B11(TX2_N)
S3_TX_100DCH2_P: 3R16.2 SITE3.A11(TX2_P)
S3_TX_100DCH3_N: 3R17.1 SITE3.B10(TX3_N)
S3_TX_100DCH3_P: 3R18.2 SITE3.A10(TX3_P)
S3_TX_100DCH4_N: 3R19.1 SITE3.A9(TX4_N)
S3_TX_100DCH4_P: 3R20.2 SITE3.B9(TX4_P)
S3_TX_100DCH5_N: 3R21.1 SITE3.A8(TX5_N)
S3_TX_100DCH5_P: 3R22.2 SITE3.B8(TX5_P)
S3_TX_100DCH6_N: 3R23.1 SITE3.A7(TX6_N)
S3_TX_100DCH6_P: 3R24.2 SITE3.B7(TX6_P)
S3_TX_100DCH7_N: 3R25.1 SITE3.B6(TX7_N)
S3_TX_100DCH7_P: 3R26.2 SITE3.A6(TX7_P)
S3_V25: 3R52.2 3R53.1
S3_VCC_I2C_Flash_18: 3C1.1 3R69.1 3R70.1 3R71.1 3R72.1 3R73.1 3R74.1 3R147.2 3R148.2 3U5.8(VCC)
S3_VDD_efuse_power: 3K48.4
S4_AUX1+: 4K9.5 4R162.1
S4_AUX1-: 4K9.4 4R161.1
S4_AUX2+: 4C54.2 4R52.1 4R54.2 4R162.2
S4_AUX2-: 4C53.2 4R51.2 4R53.2 4R161.2
S4_AUX+: 4K9.6 4K50.6 SITE4.D14(AUX_P)
S4_AUX-: 4K9.3 4K50.3 SITE4.E14(AUX_N)
S4_AUX_100DCH001+: 4K9.7
S4_AUX_100DCH001-: 4K9.2
S4_AUX_100DCH003+: 4C54.1
S4_AUX_100DCH003-: 4C53.1
S4_DCH005: SITE4.A14(HPD)
S4_DCH006: 4K10.3 SITE4.A1(RESET)
S4_DCH007: SITE4.B15(BIST)
S4_DCH009: SITE4.C15(CABC_EN)
S4_DCH010: SITE4.A15(PWMI)
S4_DCH011: SITE4.E3(PWMO)
S4_DCH012: 4K28.6 SITE4.C1(I2C_SDA)
S4_DCH013: 4K28.3 SITE4.D1(I2C_SCL)
S4_DCH014: 4K48.2
S4_DCH015: SITE4.E5(GPIO1)
S4_DCH016: SITE4.D5(GPIO2)
S4_DCH017: SITE4.D6(GPIO3)
S4_DCH018: SITE4.D7(GPIO4)
S4_DCH019: SITE4.D8(GPIO5)
S4_DCH020: SITE4.E6(GPIO6)
S4_DCH021: SITE4.D3(GPIO7)
S4_DCH022: SITE4.E4(GPIO8)
S4_DCH023: SITE4.C2(GPIO9)
S4_DCH024: SITE4.D15(GPIO10)
S4_DCH025: SITE4.B1(STV1)
S4_DCH026: SITE4.D2(STV2)
S4_DCH027: SITE4.B2(CPV)
S4_DCH028: SITE4.E1(OE1)
S4_DCH029: SITE4.E2(OE2)
S4_DCH030: SITE4.A3(XSTB)
S4_DCH031: SITE4.A2(SD_LOCK)
S4_DCH032: 4R200.2
S4_DCH033: 4R201.2
S4_DCH034: 4R202.2
S4_DCH035: 4R203.2
S4_DCH036: 4R204.2
S4_DCH037: 4R205.2
S4_DCH038: 4R206.2
S4_DCH039: 4R207.2
S4_DCH040: 4R208.2
S4_DCH041: 4R209.2
S4_DCH42: 4K15.2
S4_DCH43: 4K15.7
S4_DCH44: 4K14.2
S4_DCH45: 4K14.7
S4_DPS_F01: 4C67.1 4CA1.1 4CC1.1 4CC2.1 4CC3.1 4CC4.1 4CD1.1 4CD2.1 4CD3.1 4CD4.1 4K55.4 4R200.1 4SH1.2 4TP_VDD09_CORE.1(TP) SITE4.C4(VDD_CORE_09[1]) SITE4.C8(VDD_CORE_09[2]) SITE4.C9(VDD_CORE_09[3]) SITE4.C10(VDD_CORE_09[4])
S4_DPS_F03: 4C71.1 4CA2.1 4CC5.1 4CC6.1 4CC7.1 4CD5.1 4CD6.1 4CD7.1 4K56.4 4R55.2 4R201.1 4SH3.2 4TP_VDDIO_18.1(TP) SITE4.C5(VDD_IO_18[2]) SITE4.C6(VDD_IO_18[3]) SITE4.C11(VDD_IO_18[1])
S4_DPS_F04: 4C73.1 4CA3.1 4CC8.1 4CD8.1 4K57.9 4R202.1 4SH6.2 4TP_VDD_TX_09_HDO.1(TP) SITE4.A5(VDD_TX_09_HDO)
S4_DPS_F05: 4C75.1 4CA4.1 4CC9.1 4CD9.1 4K58.4 4R203.1 4SH7.2 4TP_VDD_TXPST_09.1(TP) SITE4.C7(VDD_TXPST_09)
S4_DPS_F06: 4C77.1 4CA5.1 4CC10.1 4CD10.1 4K58.9 4R204.1 4SH10.2 4TP_VDD_TX_09.1(TP) SITE4.A4(VDD_TX_09)
S4_DPS_F07: 4C79.1 4CA6.1 4CC11.1 4CD11.1 4K59.4 4R205.1 4SH12.2 4TP_VDDRX_AUX.1(TP) SITE4.C14(VDDRX_AUX_09)
S4_DPS_F08: 4C81.1 4CA7.1 4CC12.1 4CD12.1 4K56.9 4R206.1 4SH14.2 4TP_VDDRX_09.1(TP) SITE4.E15(VDDRX_09)
S4_DPS_F09: 4C83.1 4CA8.1 4CC13.1 4CD13.1 4K59.9 4R207.1 4SH16.2 4TP_VDD_PLL_09.1(TP) SITE4.B3(VDD_PLL_09)
S4_DPS_F10: 4C85.1 4CA9.1 4CC14.1 4CD14.1 4K55.9 4R208.1 4SH18.2 4TP_VDD_IOB_18_BOOST.1(TP) SITE4.B14(VDD_IOB_18_BOOST)
S4_DPS_F11: 4C87.1 4CA10.1 4CC15.1 4CD15.1 4K57.4 4R209.1 4SH20.2 4TP_VDD_IOB_18_POR.1(TP) SITE4.C3(VDD_IOB_18_POR)
S4_DPS_FS01: 4SH1.1
S4_DPS_FS03: 4SH3.1
S4_DPS_FS04: 4SH6.1
S4_DPS_FS05: 4SH7.1
S4_DPS_FS06: 4SH10.1
S4_DPS_FS07: 4SH12.1
S4_DPS_FS08: 4SH14.1
S4_DPS_FS09: 4SH16.1
S4_DPS_FS10: 4SH18.1
S4_DPS_FS11: 4SH20.1
S4_DPS_GS01: 4SH2.1
S4_DPS_GS03: 4SH4.1
S4_DPS_GS04: 4SH5.1
S4_DPS_GS05: 4SH8.1
S4_DPS_GS06: 4SH9.1
S4_DPS_GS07: 4SH11.1
S4_DPS_GS08: 4SH13.1
S4_DPS_GS09: 4SH15.1
S4_DPS_GS10: 4SH17.1
S4_DPS_GS11: 4SH19.1
S4_RLY01: 4K9.8(V-)
S4_RLY02: 4K50.8(V-)
S4_RLY03: 4K10.8(V-)
S4_RLY04: 4K48.8(V-)
S4_RLY08: 4K54.8(V-)
S4_RLY09: 4K61.8(V-)
S4_RLY20: 4K55.12(V-)
S4_RLY22: 4K57.12(V-)
S4_RLY24: 4K59.12(V-)
S4_RLY27: 4K15.8(V-)
S4_RLY43: 4K60.8(V-)
S4_RLY44: 4K62.8(V-)
S4_RLY45: 4K14.8(V-)
S4_RLY46: 4K28.8(V-)
S4_RLY47: 4K56.12(V-)
S4_RLY48: 4K58.12(V-)
S4_ROM_SPI_CS: 4K15.6 SITE4.E7(ROM_SPI_CS)
S4_ROM_SPI_SCK: 4K15.3 SITE4.E8(ROM_SPI_SCK)
S4_ROM_SPI_SDI: 4K14.6 SITE4.E9(ROM_SPI_SDI)
S4_ROM_SPI_SDO: 4K14.3 SITE4.D9(ROM_SPI_SDO)
S4_RX_85DCH00+: SITE4.E10(RX_N0)
S4_RX_85DCH00-: SITE4.D10(RX_P0)
S4_RX_85DCH01+: SITE4.E11(RX_N1)
S4_RX_85DCH01-: SITE4.D11(RX_P1)
S4_RX_85DCH02+: SITE4.D12(RX_N2)
S4_RX_85DCH02-: SITE4.E12(RX_P2)
S4_RX_85DCH03+: SITE4.D13(RX_N3)
S4_RX_85DCH03-: SITE4.E13(RX_P3)
S4_SPI_1_CSN: 4K15.5 4R69.2 4U5.1(CS#)
S4_SPI_1_SCK: 4K15.4 4R73.2 4U5.6(SCLK)
S4_SPI_1_SDI: 4K14.5 4R70.2 4U5.2(SO)
S4_SPI_1_SDO: 4K14.4 4R74.2 4U5.5(SI)
S4_TEST: 4K48.3 SITE4.D4(TEST)
S4_TX_100DCH0_N: 4R11.1 SITE4.A13(TX0_N)
S4_TX_100DCH0_P: 4R12.2 SITE4.B13(TX0_P)
S4_TX_100DCH1_N: 4R13.1 SITE4.B12(TX1_N)
S4_TX_100DCH1_P: 4R14.2 SITE4.A12(TX1_P)
S4_TX_100DCH2_N: 4R15.1 SITE4.B11(TX2_N)
S4_TX_100DCH2_P: 4R16.2 SITE4.A11(TX2_P)
S4_TX_100DCH3_N: 4R17.1 SITE4.B10(TX3_N)
S4_TX_100DCH3_P: 4R18.2 SITE4.A10(TX3_P)
S4_TX_100DCH4_N: 4R19.1 SITE4.A9(TX4_N)
S4_TX_100DCH4_P: 4R20.2 SITE4.B9(TX4_P)
S4_TX_100DCH5_N: 4R21.1 SITE4.A8(TX5_N)
S4_TX_100DCH5_P: 4R22.2 SITE4.B8(TX5_P)
S4_TX_100DCH6_N: 4R23.1 SITE4.A7(TX6_N)
S4_TX_100DCH6_P: 4R24.2 SITE4.B7(TX6_P)
S4_TX_100DCH7_N: 4R25.1 SITE4.B6(TX7_N)
S4_TX_100DCH7_P: 4R26.2 SITE4.A6(TX7_P)
S4_V25: 4R52.2 4R53.1
S4_VCC_I2C_Flash_18: 4C1.1 4R69.1 4R70.1 4R71.1 4R72.1 4R73.1 4R74.1 4R147.2 4R148.2 4U5.8(VCC)
S4_VDD_efuse_power: 4K48.4
UT1_UP5V: 2K9.1(V+) 2K10.1(V+) 2K14.1(V+) 2K15.1(V+) 2K28.1(V+) 2K48.1(V+) 2K50.1(V+) 2K54.1(V+) 2K55.1(V+) 2K56.1(V+) 2K57.1(V+) 2K58.1(V+) 2K59.1(V+) 2K60.1(V+) 2K61.1(V+) 2K62.1(V+) 3K9.1(V+) 3K10.1(V+) 3K14.1(V+) 3K15.1(V+) 3K28.1(V+) 3K48.1(V+) 3K50.1(V+) 3K54.1(V+) 3K55.1(V+) 3K56.1(V+) 3K57.1(V+) 3K58.1(V+) 3K59.1(V+) 3K60.1(V+) 3K61.1(V+) 3K62.1(V+) 4K9.1(V+) 4K10.1(V+) 4K14.1(V+) 4K15.1(V+) 4K28.1(V+) 4K48.1(V+) 4K50.1(V+) 4K54.1(V+) 4K55.1(V+) 4K56.1(V+) 4K57.1(V+) 4K58.1(V+) 4K59.1(V+) 4K60.1(V+) 4K61.1(V+) 4K62.1(V+) ; also on sheet 12 13 14 16 17 18 19 20 21 22 23 24
N19199259: 2K10.4 2R55.1 2SW1.1
N19199302: 2K61.5 2R22.1
N19199304: 2K61.6 2R21.2
N19199305: 2K61.4 2R20.1
N19199306: 2K61.3 2R19.2
N19199318: 2K54.5 2R14.1
N19199319: 2K54.6 2R13.2
N19199320: 2K54.4 2R12.1
N19199321: 2K54.3 2R11.2
N19199323: 2K60.5 2R18.1
N19199330: 2K60.3 2R15.2
N19199331: 2K60.4 2R16.1
N19199332: 2K60.6 2R17.2
N19199334: 2K62.5 2R26.1
N19199341: 2K62.3 2R23.2
N19199342: 2K62.4 2R24.1
N19199343: 2K62.6 2R25.2
N19199463: 2C55.2 2SW1.2
N19199473: 2K50.4 2R184.1
N19199475: 2K50.5 2R185.1
N19200862: 2R71.2 2R163.2 2U5.3(WP#)
N19200865: 2R72.2 2U5.7(HOLD#)
N19200913: 2K28.4 2R147.1
N19200914: 2K28.5 2R148.1
N19201316: 2C69.1 2K55.5
N19201318: 2C70.1 2K55.8
N19201556: 2C89.1 2K56.5
N19201559: 2C90.1 2K56.8
N19201562: 2C91.1 2K57.5
N19201565: 2C92.1 2K57.8
N19201568: 2C93.1 2K58.5
N19201571: 2C94.1 2K58.8
N19201581: 2C95.1 2K59.5
N19201583: 2C96.1 2K59.8
N19203612: 3K10.4 3R55.1 3SW1.1
N19203655: 3K61.5 3R22.1
N19203657: 3K61.6 3R21.2
N19203658: 3K61.4 3R20.1
N19203659: 3K61.3 3R19.2
N19203671: 3K54.5 3R14.1
N19203672: 3K54.6 3R13.2
N19203673: 3K54.4 3R12.1
N19203674: 3K54.3 3R11.2
N19203676: 3K60.5 3R18.1
N19203683: 3K60.3 3R15.2
N19203684: 3K60.4 3R16.1
N19203685: 3K60.6 3R17.2
N19203687: 3K62.5 3R26.1
N19203694: 3K62.3 3R23.2
N19203695: 3K62.4 3R24.1
N19203696: 3K62.6 3R25.2
N19203816: 3C55.2 3SW1.2
N19203826: 3K50.4 3R184.1
N19203828: 3K50.5 3R185.1
N19205215: 3R71.2 3R163.2 3U5.3(WP#)
N19205218: 3R72.2 3U5.7(HOLD#)
N19205266: 3K28.4 3R147.1
N19205267: 3K28.5 3R148.1
N19205669: 3C69.1 3K55.5
N19205671: 3C70.1 3K55.8
N19205909: 3C89.1 3K56.5
N19205912: 3C90.1 3K56.8
N19205915: 3C91.1 3K57.5
N19205918: 3C92.1 3K57.8
N19205921: 3C93.1 3K58.5
N19205924: 3C94.1 3K58.8
N19205934: 3C95.1 3K59.5
N19205936: 3C96.1 3K59.8
N19207965: 4K10.4 4R55.1 4SW1.1
N19208008: 4K61.5 4R22.1
N19208010: 4K61.6 4R21.2
N19208011: 4K61.4 4R20.1
N19208012: 4K61.3 4R19.2
N19208024: 4K54.5 4R14.1
N19208025: 4K54.6 4R13.2
N19208026: 4K54.4 4R12.1
N19208027: 4K54.3 4R11.2
N19208029: 4K60.5 4R18.1
N19208036: 4K60.3 4R15.2
N19208037: 4K60.4 4R16.1
N19208038: 4K60.6 4R17.2
N19208040: 4K62.5 4R26.1
N19208047: 4K62.3 4R23.2
N19208048: 4K62.4 4R24.1
N19208049: 4K62.6 4R25.2
N19208169: 4C55.2 4SW1.2
N19208179: 4K50.4 4R184.1
N19208181: 4K50.5 4R185.1
N19209568: 4R71.2 4R163.2 4U5.3(WP#)
N19209571: 4R72.2 4U5.7(HOLD#)
N19209619: 4K28.4 4R147.1
N19209620: 4K28.5 4R148.1
N19210022: 4C69.1 4K55.5
N19210024: 4C70.1 4K55.8
N19210262: 4C89.1 4K56.5
N19210265: 4C90.1 4K56.8
N19210268: 4C91.1 4K57.5
N19210271: 4C92.1 4K57.8
N19210274: 4C93.1 4K58.5
N19210277: 4C94.1 4K58.8
N19210287: 4C95.1 4K59.5
N19210289: 4C96.1 4K59.8

Not connected (* = marked no-connect by the designer): 2K10 2* 5* 6* 7*; 2K28 2* 7*; 2K48 5* 6* 7*; 2K50 2* 7*; 2K54 2* 7*; 2K55 3* 10*; 2K56 3* 10*; 2K57 3* 10*; 2K58 3* 10*; 2K59 3* 10*; 2K60 2* 7*; 2K61 2* 7*; 2K62 2* 7*; 2UF1 1*; 3K10 2* 5* 6* 7*; 3K28 2* 7*; 3K48 5* 6* 7*; 3K50 2* 7*; 3K54 2* 7*; 3K55 3* 10*; 3K56 3* 10*; 3K57 3* 10*; 3K58 3* 10*; 3K59 3* 10*; 3K60 2* 7*; 3K61 2* 7*; 3K62 2* 7*; 3UF1 1*; 4K10 2* 5* 6* 7*; 4K28 2* 7*; 4K48 5* 6* 7*; 4K50 2* 7*; 4K54 2* 7*; 4K55 3* 10*; 4K56 3* 10*; 4K57 3* 10*; 4K58 3* 10*; 4K59 3* 10*; 4K60 2* 7*; 4K61 2* 7*; 4K62 2* 7*; 4UF1 1*; SITE2 NGH1* NGH2* NGH3* NGH4* NUT1* NUT2* NUT3* NUT4*; SITE3 NGH1* NGH2* NGH3* NGH4* NUT1* NUT2* NUT3* NUT4*; SITE4 NGH1* NGH2* NGH3* NGH4* NUT1* NUT2* NUT3* NUT4*

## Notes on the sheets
sheet 1
- CAP Reference :
  CD*-->Place on TOP¡Fclose to PIN
  CC*-->Place on TOP¡Fclose to PIN
  CA*-->Place on TOP¡Fclose to ATE
- RLY close to ATE
  C*--> Place on Bot ; Close RELAY
- <2A
- PIN
- C4
  C8
  C9
  C10
- <200mA
- PIN
- C5
  C6
  C11
- <200mA
- PIN
- A5
- <200mA
- PIN
- C7
- <200mA
- PIN
- A4
- <200mA
- PIN
- C14
- <200mA
- PIN
- E15
- <200mA
- PIN
- B3
- <200mA
- PIN
- B14
- <200mA
- PIN
- C3
sheet 2
- FLASH
- Flash uses MX25U4035FM1I-SOP8
- ¡°Please note that Flash uses the shortest path
  and all sites have the same length.
  **Line length < 4000MIL
- I2C
sheet 3
- ISP TX 2.7Gbps
- EDP RX 5.4Gbps
- ISP TX 2.7Gbps
- DIFF 85 Ohm
- DIFF 100 Ohm
- Swap P/N (P=+, N=-) to prevent RX routing from impacting trace length
  IC PIN - RX_P0 connected to Test Channel - 85DCH-
  IC PIN - RX_N0 connected toTest Channel - 85DCH+
  IC PIN - RX_P1 connected to Test Channel - 85DCH-
  IC PIN - RX_N1 connected to Test Channel - 85DCH+
  IC PIN - RX_P2 connected to Test Channel - 85DCH-
  IC PIN - RX_N2 connected to Test Channel - 85DCH+
  IC PIN - RX_P3 connected to Test Channel - 85DCH-
  IC PIN - RX_N3 connected to Test Channel - 85DCH+
- TEST
- AUX
- DIFF 100 Ohm
- Close to DUT
- Close to DUT
- Close to Base
- DIFF 100 Ohm
- DIFF 100 Ohm
- The DUT~CH trace width 20 mil
- RST
- 2026 11/2  jumper to DIP switch
sheet 4
- CAP Reference :
  CD*-->Place on TOP¡Fclose to PIN
  CC*-->Place on TOP¡Fclose to PIN
  CA*-->Place on TOP¡Fclose to ATE
- RLY close to ATE
  C*--> Place on Bot ; Close RELAY
- <2A
- PIN
- C4
  C8
  C9
  C10
- <200mA
- PIN
- C5
  C6
  C11
- <200mA
- PIN
- A5
- <200mA
- PIN
- C7
- <200mA
- PIN
- A4
- <200mA
- PIN
- C14
- <200mA
- PIN
- E15
- <200mA
- PIN
- B3
- <200mA
- PIN
- B14
- <200mA
- PIN
- C3
sheet 5
- FLASH
- Flash uses MX25U4035FM1I-SOP8
- ¡°Please note that Flash uses the shortest path
  and all sites have the same length.
  **Line length < 4000MIL
- I2C
sheet 6
- ISP TX 2.7Gbps
- EDP RX 5.4Gbps
- ISP TX 2.7Gbps
- DIFF 85 Ohm
- DIFF 100 Ohm
- Swap P/N (P=+, N=-) to prevent RX routing from impacting trace length
  IC PIN - RX_P0 connected to Test Channel - 85DCH-
  IC PIN - RX_N0 connected toTest Channel - 85DCH+
  IC PIN - RX_P1 connected to Test Channel - 85DCH-
  IC PIN - RX_N1 connected to Test Channel - 85DCH+
  IC PIN - RX_P2 connected to Test Channel - 85DCH-
  IC PIN - RX_N2 connected to Test Channel - 85DCH+
  IC PIN - RX_P3 connected to Test Channel - 85DCH-
  IC PIN - RX_N3 connected to Test Channel - 85DCH+
- TEST
- AUX
- DIFF 100 Ohm
- Close to DUT
- Close to DUT
- Close to Base
- DIFF 100 Ohm
- DIFF 100 Ohm
- The DUT~CH trace width 20 mil
- RST
- 2026 11/2  jumper to DIP switch
sheet 7
- CAP Reference :
  CD*-->Place on TOP¡Fclose to PIN
  CC*-->Place on TOP¡Fclose to PIN
  CA*-->Place on TOP¡Fclose to ATE
- RLY close to ATE
  C*--> Place on Bot ; Close RELAY
- <2A
- PIN
- C4
  C8
  C9
  C10
- <200mA
- PIN
- C5
  C6
  C11
- <200mA
- PIN
- A5
- <200mA
- PIN
- C7
- <200mA
- PIN
- A4
- <200mA
- PIN
- C14
- <200mA
- PIN
- E15
- <200mA
- PIN
- B3
- <200mA
- PIN
- B14
- <200mA
- PIN
- C3
sheet 8
- FLASH
- Flash uses MX25U4035FM1I-SOP8
- ¡°Please note that Flash uses the shortest path
  and all sites have the same length.
  **Line length < 4000MIL
- I2C
sheet 9
- ISP TX 2.7Gbps
- EDP RX 5.4Gbps
- ISP TX 2.7Gbps
- DIFF 85 Ohm
- DIFF 100 Ohm
- Swap P/N (P=+, N=-) to prevent RX routing from impacting trace length
  IC PIN - RX_P0 connected to Test Channel - 85DCH-
  IC PIN - RX_N0 connected toTest Channel - 85DCH+
  IC PIN - RX_P1 connected to Test Channel - 85DCH-
  IC PIN - RX_N1 connected to Test Channel - 85DCH+
  IC PIN - RX_P2 connected to Test Channel - 85DCH-
  IC PIN - RX_N2 connected to Test Channel - 85DCH+
  IC PIN - RX_P3 connected to Test Channel - 85DCH-
  IC PIN - RX_N3 connected to Test Channel - 85DCH+
- TEST
- AUX
- DIFF 100 Ohm
- Close to DUT
- Close to DUT
- Close to Base
- DIFF 100 Ohm
- DIFF 100 Ohm
- The DUT~CH trace width 20 mil
- RST
- 2026 11/2  jumper to DIP switch
